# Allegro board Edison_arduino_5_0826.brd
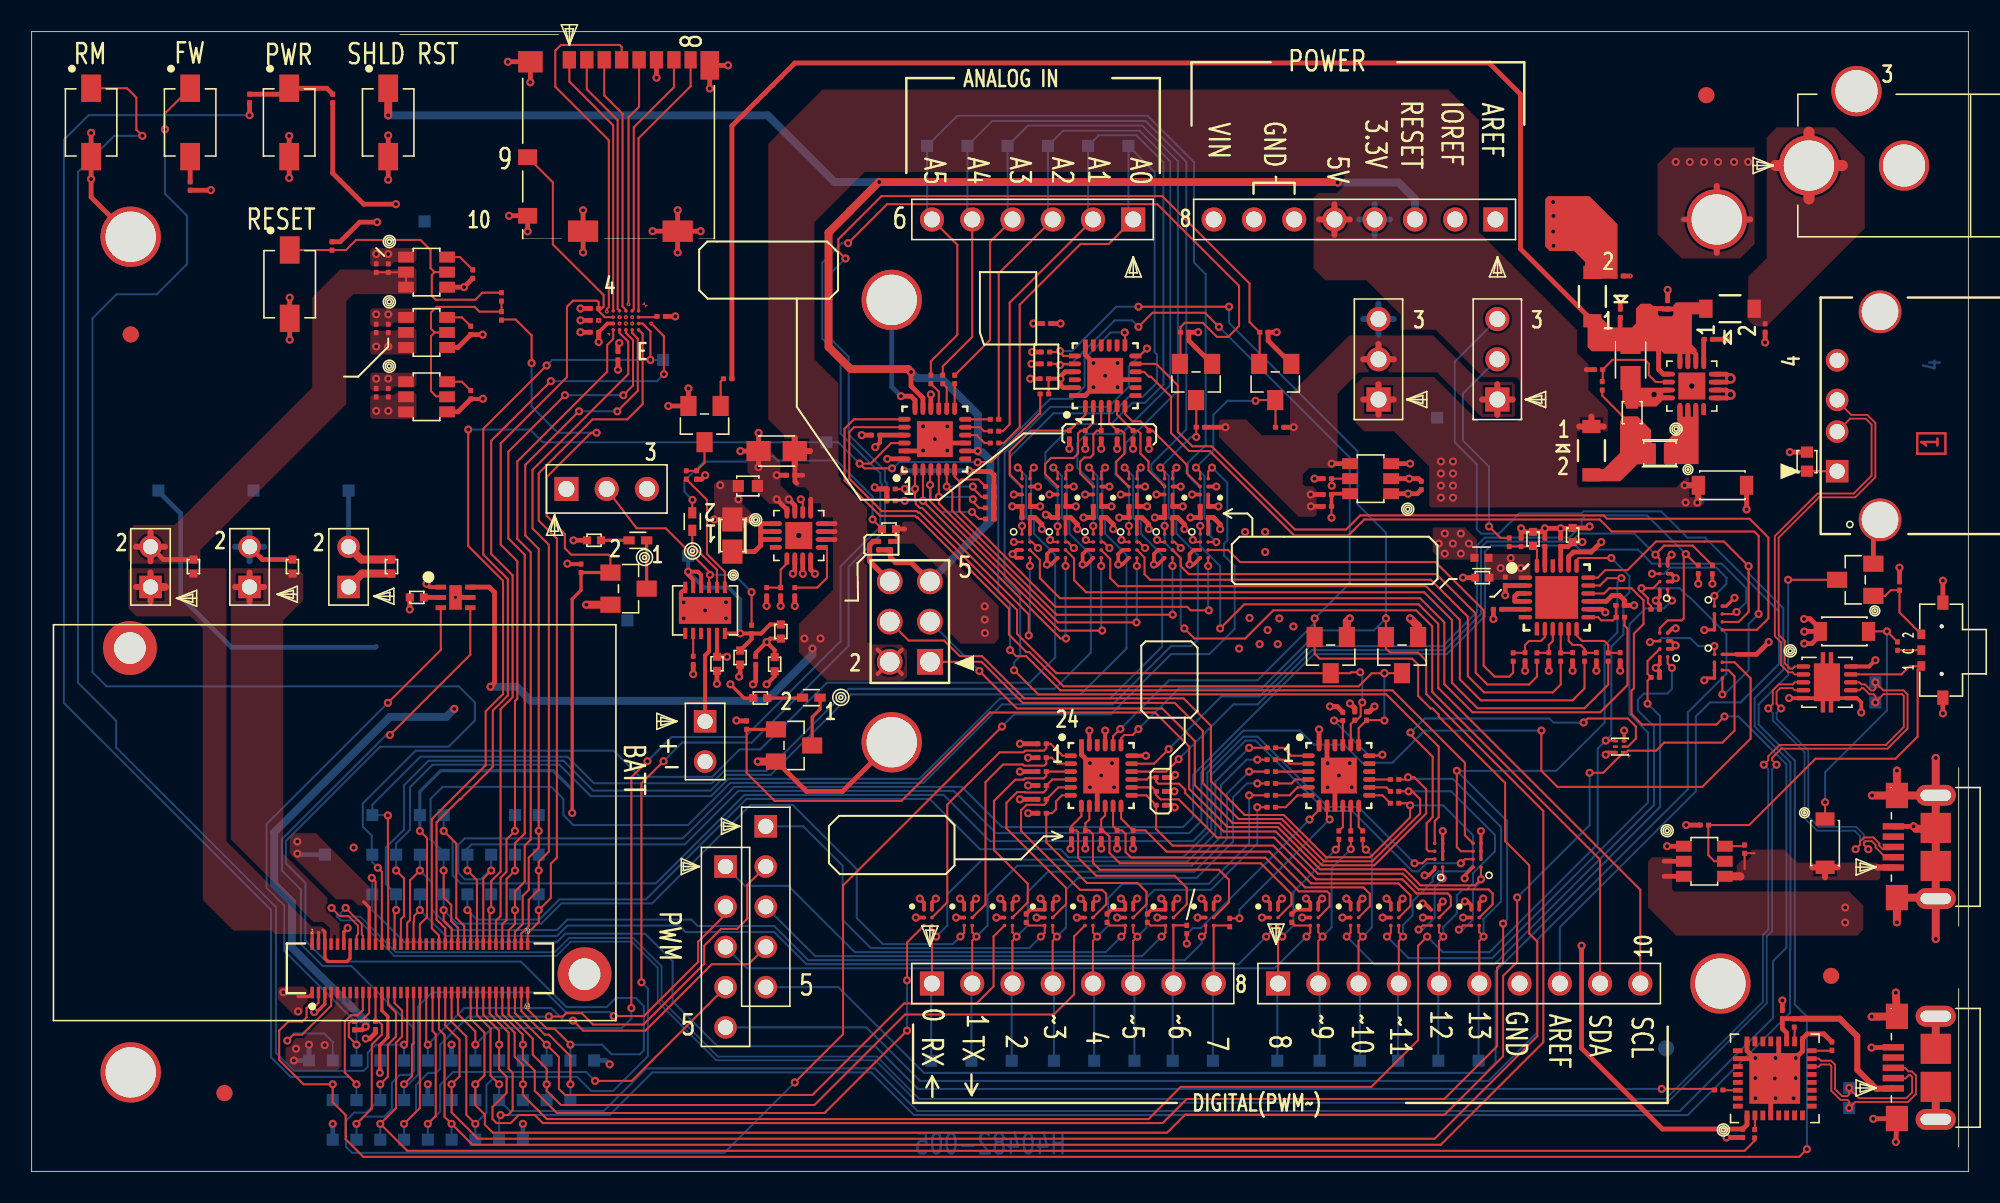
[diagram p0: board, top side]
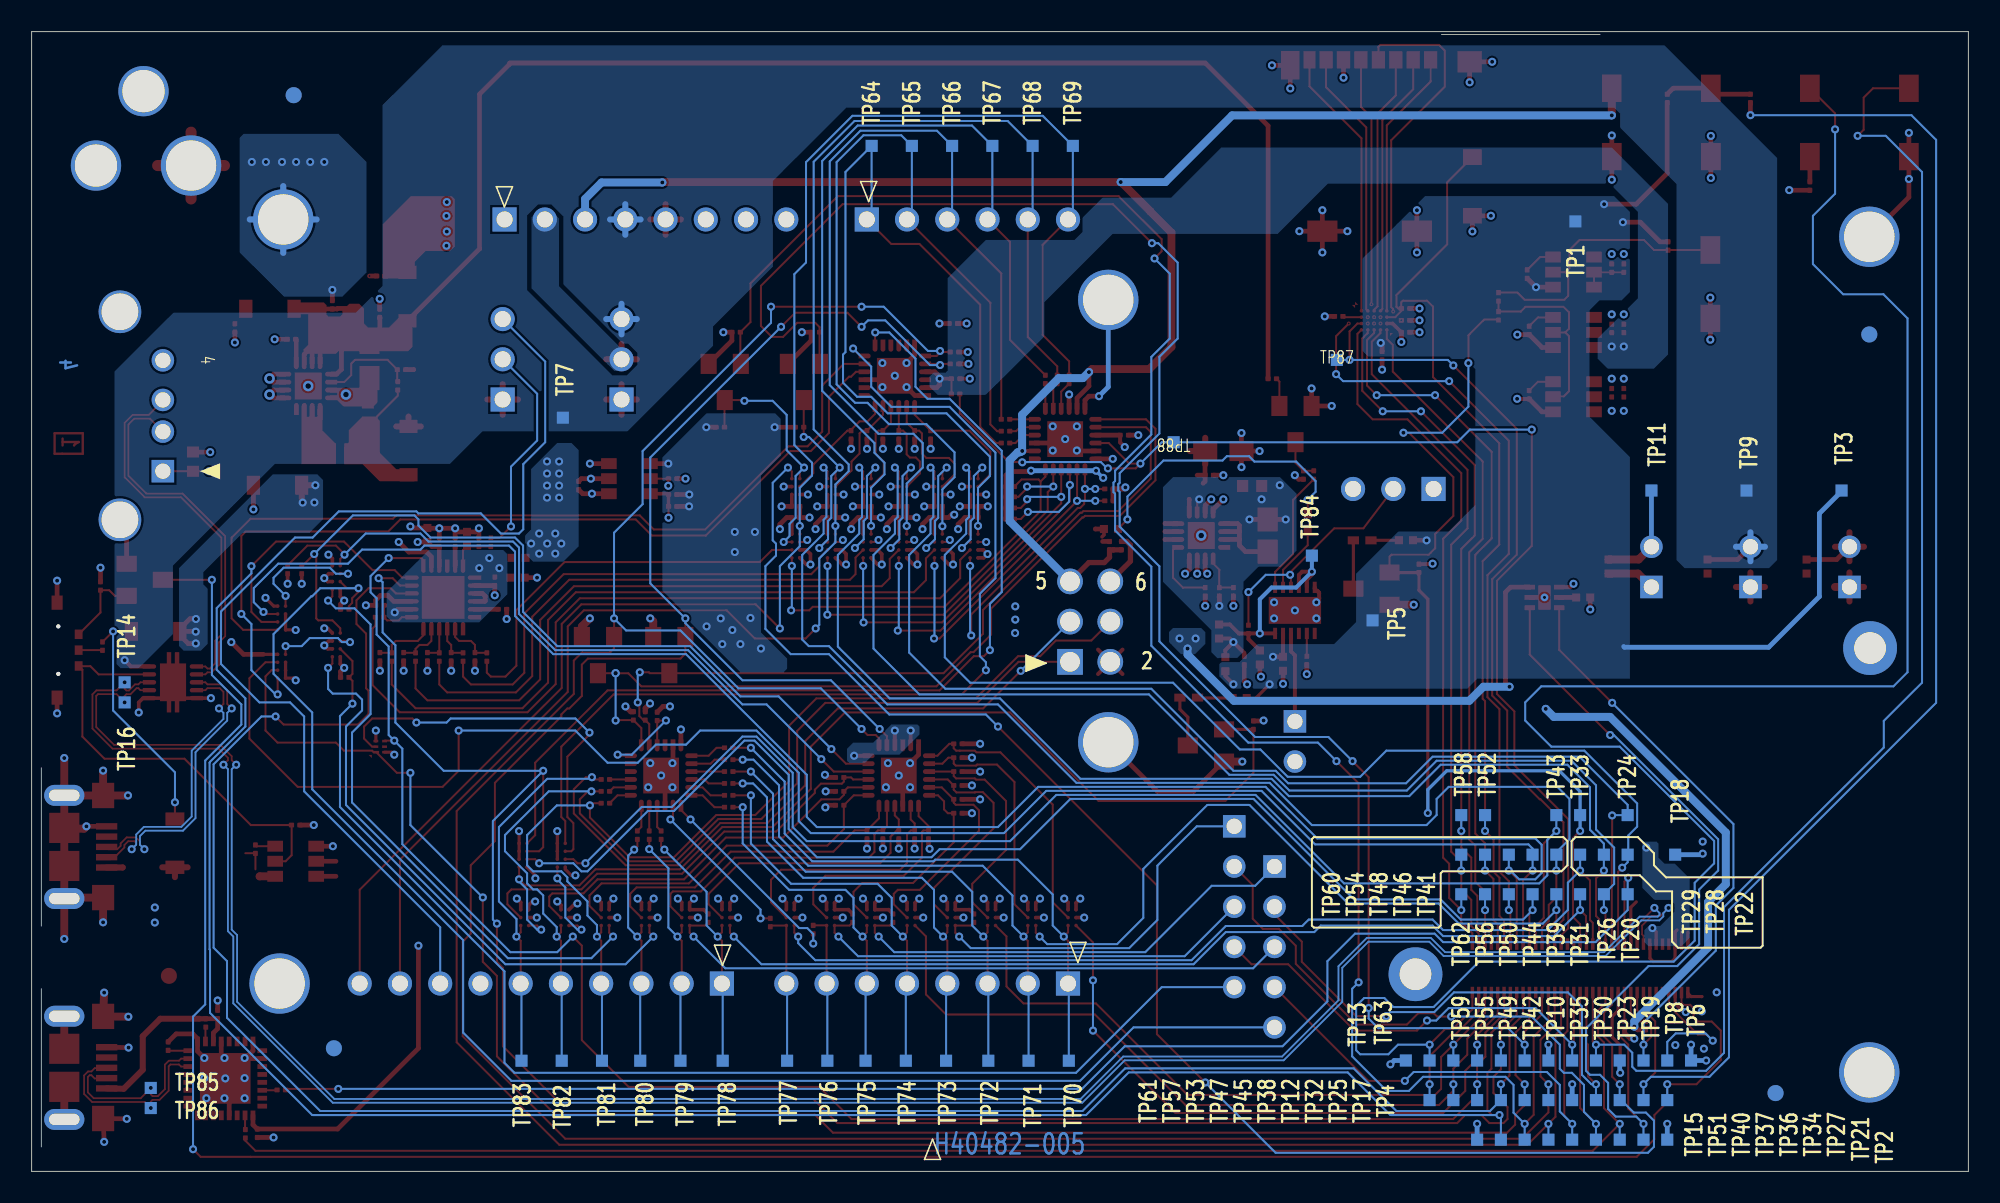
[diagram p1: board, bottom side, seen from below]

Outline 122.22 x 71.98 mm; copper layers: TOP, GND, PWR_GND, BOTTOM. Coordinates in mm from the lower left corner of the outline.
Outline path: 33.25,71.81 23.24,71.81 ; 0,71.98 0,0 122.22,0 122.22,71.98 0,71.98

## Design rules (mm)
constraint set DEFAULT: min track width 0.127
net group DP1: nets N30245034 N30246500
net group PWR_GND: nets V_VBAT_BKUP VBUS_2
net group USB_D: nets USB_DN USB_DP
net group USBA: nets USBA_CONN_DN USBA_CONN_DP
net group USBD: nets N11374 N11378

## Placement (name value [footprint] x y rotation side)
C1  22UF  [SMC0603_HI_VALUE]  101.01 47.32 180 top
C3  0.1uF  [C0201]  103.25 55 0 top
C4  33000pF  [SMC0201]  105.83 52.55 0 top
C5  10uF  [SMC0402]  43.25 32.5 0 top
C6  0.1uF  [C0201]  45.7 32 180 top
C8  10uF  [SMC0402]  44.71 32.9 0 top
C9  0.1uF  [C0201]  110.49 10.17 0 top
C10  0.1uF  [C0201]  107.99 2.14 180 top
C11  10uF  [SMC0402]  92 37.5 270 top
C12  0.1uF  [C0201]  93 37 180 top
C13  10uF  [SMC0402]  97.25 39.75 180 top
C14  0.1uF  [C0201]  96.5 40 0 top
C15  0.1uF  [C0201]  73.75 42 90 top
C16  0.1uF  [C0201]  71.5 42 90 top
C17  0.1uF  [C0201]  69.25 42 90 top
C18  0.1uF  [C0201]  67 42 90 top
C19  0.1uF  [C0201]  64.75 42 90 top
C20  0.1uF  [C0201]  62.5 42 90 top
C21  0.1uF  [C0201]  63.64 50.06 90 top
C22  0.1uF  [C0201]  64.32 53.55 270 top
C23  0.1uF  [C0201]  62.5 41.3 90 top
C24  0.1uF  [C0201]  64.75 41.3 90 top
C25  0.1uF  [C0201]  73.75 41.3 90 top
C26  0.1uF  [C0201]  53 46.5 90 top
C27  0.1uF  [C0201]  82.75 29 0 top
C28  0.1uF  [C0201]  67 41.3 90 top
C29  0.1uF  [C0201]  71.5 41.3 90 top
C30  0.1uF  [C0201]  69.25 41.3 90 top
C31  0.1uF  [C0201]  35.25 53 90 top
C32  0.1uF  [C0201]  37 51.25 180 top
C33  0.1uF  [C0201]  35.25 53.75 90 top
C34  100pF  [SMC0201]  53.45 39.52 90 top
C36  2.2uF  [SMC0603_HI_VALUE]  112.04 44.22 180 top
C40  100pF  [SMC0201]  100.25 35.75 0 top
C41  100pF  [SMC0201]  100.25 32.5 270 top
C42  100pF  [SMC0201]  98.75 32.5 270 top
C43  100pF  [SMC0201]  97.25 32.5 270 top
C44  100pF  [SMC0201]  95.75 32.5 270 top
C45  100pF  [SMC0201]  94.25 32.5 270 top
C46  10uF  [SMC0402]  94.75 39.5 180 top
C47  10uF  [SMC0805]  100.91 52.39 0 top
C48  0.1uF  [C0201]  113.61 8.17 0 top
C49  0.1uF  [C0201]  21.74 57.32 0 top
C50  0.1uF  [C0201]  21.74 53.51 0 top
C51  0.1uF  [C0201]  22.51 49.44 0 top
C52  0.1uF  [C0201]  47.64 43.97 90 top
C53  33000pF  [SMC0201]  48.16 36.6 270 top
C54  22UF  [SMC0603_HI_VALUE]  44.6 43.29 90 top
C55  10uF  [SMC0805]  48.16 45.49 270 top
C56  0.1uF  [C0201]  109.4 53 180 top
C57  0.1uF  [C0201]  100.45 56.55 270 top
CR1  RB160M-40  [SOD123_67X106]  105.18 43.33 90 top
CR2  D2BW319000  [SCR_27X17MA]  98.44 45.52 0 top
CR6  D2BW319000  [SCR_27X17MA]  98.5 55.25 180 top
CR7  D2BW319000  [SCR_27X17MA]  107.19 54.48 90 top
CR8  RB160M-40  [SOD123_67X106]  113.18 22.25 0 top
CR9  RB160M-40  [SOD123_67X106]  115.93 34.1 270 top
DS1  GREEN  [SMLED0402]  38.81 39.85 270 top
DS2  GREEN  [SMLED0402]  49.76 29.92 270 top
DS3  GREEN  [SMLED0402]  41.69 40.49 180 top
EU1  TS3USB221  [LCC10_P5MM_EP65X94]  111.83 31.89 0 top
FB1  120 Ohm@100MHz  [SMF0402]  91.5 38.75 180 top
J1  DC_JACK  [JK_3P_RA]  112.17 63.53 270 top
J1A1  6Pin_HDR  [1X6RCPT_2P54_VT_TH]  63.17 60.12 180 top
J1B1  CON8_HDR  [1X8RCPT_2P54_VT_TH]  65.71 11.86 0 top
J2  CON2_HDR  [102276-001]  42.5 28.42 0 top
J2A1  CON8_HDR  [1X8RCPT_2P54_VT_TH]  83.49 60.12 180 top
J2B1  1x10  [1X10RCPT_2P54_VT_TH]  90.09 11.86 0 top
J3  G58911-001  [RCPT_USB_5P_DIP_SM]  120.17 6.54 90 top
J4  2X3HDR  [CONN6_H18587001]  56.69 32.18 180 top
J5  SD CONN  G46739-001  [CONN_SDCARD_8P_PP]  37.04 64.77 180 top
J6  D23040-001  [CONN4_D23040001]  113.95 44.22 90 top
J7  70Pin BTB  Socket HIROSE DF40  [2X35_P4MM_BTB_AXT_SKT_MB]  17.7 11.29 0 top
J8  CON3_HDR  [102276-003]  92.5 48.75 180 top
J9  CON3_HDR  [102276-003]  85 48.75 180 top
J10  CON2_HDR  [102276-001]  7.5 36.91 180 top
J11  1X5_HDR  [102276-005]  43.79 19.25 0 top
J12  1X5_HDR  [102276-005]  46.33 21.79 0 top
J13  CON3_HDR  [102276-003]  33.75 43.1 90 top
J14  CON2_HDR  [102276-001]  13.75 36.91 180 top
J15  CON2_HDR  [102276-001]  20 36.91 180 top
J16  G58911-001  [RCPT_USB_5P_DIP_SM]  120.17 20.49 90 top
L1  1uH  [SML0805]  103.77 45.35 270 top
L2  1uH  [SML0805]  44.22 39.14 180 top
MGT5  NPTH125  [SYMBOL_NPTH125]  6.25 59.03 0 top
MTG1  -  [NPIN787]  6.2 33.05 0 top
MTG2  -  [NPIN787]  34.89 12.45 0 top
MTG3  NPTH125  [SYMBOL_NPTH125]  106.35 60.12 0 top
MTG4  NPTH125  [SYMBOL_NPTH125]  106.58 11.86 0 top
MTG6  NPTH125  [SYMBOL_NPTH125]  6.25 6.25 0 top
MTG7  NPTH125  [SYMBOL_NPTH125]  54.28 55.04 0 top
MTG8  NPTH125  [SYMBOL_NPTH125]  54.28 27.1 0 top
NOREF  -  []  73.75 38.75 0 top
NOREF#2  -  []  65.25 39.75 90 top
NOREF#3  -  []  66.79 38.54 0 top
NOREF#4  -  []  88.55 19.22 90 top
NOREF#5  -  []  71.5 38.75 0 top
NOREF#6  -  []  62.5 38.75 0 top
NOREF#7  -  []  106.2 31.15 0 top
NOREF#8  -  []  73.54 38.54 0 top
NOREF#9  -  []  0 0 0 top
NOREF#10  -  []  106.7 32.15 90 top
NOREF#11  -  []  102.75 34 0 top
NOREF#12  -  []  102.54 34.21 0 top
NOREF#13  -  []  91.67 19.01 90 top
NOREF#14  -  []  103.46 38.46 270 top
NOREF#15  -  []  105.99 30.95 90 top
NOREF#16  -  []  67 38.75 0 top
NOREF#17  -  []  73.54 38.54 90 top
NOREF#18  -  []  74.25 39.75 90 top
NOREF#19  -  [unnamed#2]  12.17 4.94 0 top
NOREF#20  -  [unnamed#2]  6.25 52.86 0 top
NOREF#21  -  []  103.46 34.21 270 top
NOREF#22  -  []  90.75 20.93 0 top
NOREF#23  -  []  64.54 38.54 0 top
NOREF#24  -  []  71.29 38.54 90 top
NOREF#25  -  []  67.5 39.75 90 top
NOREF#26  -  []  69.25 38.75 0 top
NOREF#27  -  []  69.75 39.75 90 top
NOREF#28  -  []  102.75 33 270 top
NOREF#29  -  []  106.7 35.2 90 top
NOREF#30  -  []  90.96 19.22 90 top
NOREF#31  -  []  89.26 19.01 90 top
NOREF#32  -  []  105.99 33.99 90 top
NOREF#33  -  []  88.55 20.72 0 top
NOREF#34  -  []  105.99 33.99 0 top
NOREF#35  -  []  6.25 6.25 0 top
NOREF#36  -  []  106.35 60.12 0 top
NOREF#37  -  []  63 39.75 90 top
NOREF#38  -  []  71.29 38.54 0 top
NOREF#39  -  []  122.22 71.98 0 top
NOREF#40  -  []  69.04 38.54 0 top
NOREF#41  -  []  105.99 30.95 0 top
NOREF#42  -  []  88.34 20.93 0 top
NOREF#43  -  []  122.22 71.98 0 top
NOREF#44  -  []  90.96 20.72 0 top
NOREF#45  -  []  64.75 38.75 0 top
NOREF#46  -  []  106.35 60.12 0 top
NOREF#47  -  []  0 0 0 top
NOREF#48  -  []  62.29 38.54 90 top
NOREF#49  -  []  64.54 38.54 90 top
NOREF#50  -  []  6.25 6.25 0 top
NOREF#51  -  []  106.2 34.2 0 top
NOREF#52  -  []  72 39.75 90 top
NOREF#53  -  [unnamed#2]  105.69 67.97 0 top
NOREF#54  -  []  102.54 38.46 0 top
NOREF#55  -  []  66.79 38.54 90 top
NOREF#56  -  []  102.75 37.25 270 top
NOREF#57  -  []  102.75 38.25 0 top
NOREF#58  -  [unnamed#2]  113.56 12.35 0 top
NOREF#59  -  []  69.04 38.54 90 top
NOREF#60  -  []  62.29 38.54 0 top
NOREF#61  -  [unnamed#2]  103.15 7.77 180 bottom
NOREF#62  -  [unnamed#2]  105.69 67.97 180 bottom
NOREF#63  -  [unnamed#2]  6.25 52.86 180 bottom
NOREF#64  -  [unnamed#2]  12.17 4.94 180 bottom
Q2  BSS138  [SOT23]  43.48 48.34 270 top
Q3  BSS138  [SOT23]  79.5 51 270 top
Q4  BSS138  [SOT23]  74.5 51 270 top
Q5  BSS138  [SOT23]  83 33.75 270 top
Q6  BSS138  [SOT23]  87.5 33.75 270 top
Q7  FDC6331L  [SOT23_6_SUPER_NOEP_1P22H]  84.5 43.75 180 top
Q8  BSS138  [SOT23]  36.53 37.82 0 top
Q9  BSS138  [SOT23]  46.97 27.91 0 top
Q10  FDC6331L  [SOT23_6_SUPER_NOEP_1P22H]  105.56 19.59 0 top
Q11  BSS138  [SOT23]  116.23 36.35 180 top
Q12  FDC6331L  [SOT23_6_SUPER_NOEP_1P22H]  24.92 48.92 0 top
Q13  FDC6331L  [SOT23_6_SUPER_NOEP_1P22H]  24.92 52.99 0 top
Q14  FDC6331L  [SOT23_6_SUPER_NOEP_1P22H]  24.92 56.8 0 top
R1  0R  [R0201]  99.12 49.88 0 top
R2  0R  [R0201]  99.15 50.64 270 top
R3  10K  [SMR0201]  43.66 50.06 90 top
R4  10K  [SMR0201]  41.75 32 180 top
R5  1K  [R0201]  41.31 44.25 0 top
R6  0R  [R0201]  41.96 44.25 0 top
R7  0R  [R0201]  106.74 5.14 270 top
R8  0R  [R0201]  111.24 9.64 0 top
R9  0R  [R0201]  108.74 2.64 0 top
R10  0R  [R0201]  92.25 35.5 90 top
R11  0R  [R0201]  95.5 40 0 top
R12  10K  [SMR0201]  81.5 42.75 90 top
R13  10K  [SMR0201]  65.49 46.25 180 top
R14  10K  [SMR0201]  66.5 46.25 180 top
R15  10K  [SMR0201]  67.5 46.25 180 top
R16  10K  [SMR0201]  68.5 46.25 180 top
R17  10K  [SMR0201]  69.51 46.25 180 top
R18  10K  [SMR0201]  70.51 46.25 180 top
R19  10K  [SMR0201]  54.2 39.25 180 top
R20  10K  [SMR0201]  63.5 27 90 top
R21  10K  [SMR0201]  63.5 26.13 90 top
R22  10K  [SMR0201]  63.5 25.25 90 top
R23  10K  [SMR0201]  63.5 24.37 90 top
R24  10K  [SMR0201]  63.5 23.5 90 top
R25  10K  [SMR0201]  71.5 24.88 270 top
R26  10K  [SMR0201]  63.5 22.62 90 top
R27  10K  [SMR0201]  71.5 24 270 top
R28  10K  [SMR0201]  65.62 21 180 top
R29  10K  [SMR0201]  71.5 23.12 270 top
R30  10K  [SMR0201]  69.51 21 180 top
R31  10K  [SMR0201]  68.5 21 180 top
R32  10K  [SMR0201]  67.5 21 180 top
R33  10K  [SMR0201]  66.5 21 180 top
R34  10K  [SMR0201]  81.5 42 90 top
R35  10K  [SMR0201]  81.5 43.75 90 top
R36  10K  [SMR0201]  20.37 9.47 0 top
R37  100K  [SMR0201]  21.69 9.48 0 top
R38  576  [SMR0402]  24.75 36.25 270 top
R39  4.7K  [SMR0201]  77.5 53 90 top
R40  4.7K  [SMR0201]  72.5 53 90 top
R41  4.7K  [SMR0201]  78.5 47 90 top
R42  4.7K  [SMR0201]  73.5 47 90 top
R43  4.7K  [SMR0201]  64.25 51 270 top
R44  4.7K  [SMR0201]  64.25 51.75 270 top
R45  10K  [SMR0201]  35.25 54.5 90 top
R46  10K  [SMR0201]  40 54 270 top
R47  220  [SMR0201]  10 62.5 0 top
R48  10K  [SMR0201]  19 67.5 180 top
R49  220  [SMR0201]  13.75 67.5 180 top
R50  4.7K  [SMR0201]  83.5 28.5 180 top
R51  4.7K  [SMR0201]  84.25 28.5 180 top
R52  47K  [SMR0201]  60.5 46 90 top
R53  47K  [SMR0201]  60.5 46.75 90 top
R54  47K  [SMR0201]  60.5 47.5 90 top
R55  47K  [SMR0201]  58.25 49.75 180 top
R56  47K  [SMR0201]  57.5 49.75 180 top
R57  47K  [SMR0201]  56.75 49.75 180 top
R58  47K  [SMR0201]  82.5 21.5 0 top
R59  47K  [SMR0201]  83.25 21.5 0 top
R60  47K  [SMR0201]  84 21.5 0 top
R61  47K  [SMR0201]  85.75 23.25 90 top
R62  47K  [SMR0201]  85.75 24 90 top
R63  47K  [SMR0201]  85.75 24.75 90 top
R64  47K  [SMR0201]  78.5 26.75 270 top
R65  47K  [SMR0201]  78.5 26 270 top
R66  47K  [SMR0201]  78.5 25.25 270 top
R67  47K  [SMR0201]  78.5 24.5 270 top
R68  47K  [SMR0201]  78.5 23.75 270 top
R69  47K  [SMR0201]  78.5 23 270 top
R70  47K  [SMR0201]  72.9 15 180 top
R71  47K  [SMR0201]  75.61 15.98 0 top
R72  2K  [SMR0201]  93.25 40 0 top
R73  2K  [SMR0201]  94 40 0 top
R74  33.2  [SMR0201]  100 35 90 top
R75  33.2  [SMR0201]  99.5 32.75 0 top
R76  33.2  [SMR0201]  98 32.75 0 top
R77  33.2  [SMR0201]  96.5 32.75 0 top
R78  33.2  [SMR0201]  95 32.75 0 top
R79  33.2  [SMR0201]  93.5 32.75 0 top
R80  10K  [SMR0201]  100.26 54.46 0 top
R81  10K  [SMR0201]  45.43 34.5 0 top
R82  100mOhm  [SMR0402]  22.71 38.64 0 top
R83  100mOhm  [SMR0402]  16.46 38.64 0 top
R84  100mOhm  [SMR0402]  10.21 38.64 0 top
R85  10K  [SMR0201]  34.67 37.82 180 top
R86  576  [SMR0402]  35.94 39.86 270 top
R87  10K  [SMR0201]  45.12 27.91 180 top
R88  576  [SMR0402]  46.43 29.9 270 top
R89  47K  [SMR0201]  70.41 15.72 180 top
R90  47K  [SMR0201]  67.87 15.72 180 top
R91  47K  [SMR0201]  62.76 15.72 180 top
R92  47K  [SMR0201]  79.53 15.72 180 top
R93  47K  [SMR0201]  102.2 35.5 90 top
R94  47K  [SMR0201]  102.2 31.2 90 top
R95  10K  [SMR0201]  105.3 21.87 90 top
R96  10K  [SMR0201]  108.1 20.08 180 top
R97  10K  [SMR0201]  117.76 32.91 180 top
R98  10K  [SMR0201]  117.88 37.24 0 top
R100  10K  [SMR0201]  27.71 48.78 180 top
R102  10K  [SMR0201]  27.71 52.85 180 top
R104  10K  [SMR0201]  27.84 56.4 180 top
R105  10K  [SMR0201]  18.95 58.71 0 top
R106  10K  [SMR0201]  22.51 56.78 180 top
R107  10K  [SMR0201]  22.51 52.97 180 top
R108  4.7K  [SMR0201]  21.74 48.91 180 top
R109  10K  [SMR0201]  106.07 37.75 180 top
R110  10K  [SMR0201]  105.18 37.75 180 top
R111  47K  [SMR0201]  47.27 36.87 0 top
R112  10.5K  [SMR0201]  46.38 36.34 180 top
R113  100mOhm  [SMR0402]  46.89 32.48 0 top
R114  576  [SMR0402]  53.66 40.57 90 top
R115  100mOhm  [SMR0402]  47.28 33.65 180 top
R116  47K  [SMR0201]  54.5 43.1 270 top
R117  47K  [SMR0201]  54.5 42.35 270 top
R118  47K  [SMR0201]  60.2 41.2 90 top
R119  47K  [SMR0201]  60.2 41.9 90 top
R120  47K  [SMR0201]  60.2 42.6 90 top
R121  47K  [SMR0201]  60.2 43.25 90 top
R122  4.7K  [SMR0201]  63.65 49.1 90 top
R123  0R  [R0201]  29.65 54.3 0 top
R124  0R  [R0201]  29.65 55.5 0 top
R125  4.7K  [SMR0201]  87.7 43.05 180 top
SW1  Slide switch,SSAJ110100  [SW_SSAJ110100_3P]  119.26 32.92 90 top
SW1UI1  LIGHT TOUCH SWITCH EVQP7J01P  [SSW2RPB]  22.5 66.25 0 top
SW1UI2  LIGHT TOUCH SWITCH EVQP7J01P  [SSW2RPB]  16.25 66.25 0 top
SW1UI3  LIGHT TOUCH SWITCH EVQP7J01P  [SSW2RPB]  10 66.25 0 top
SW1UI4  LIGHT TOUCH SWITCH EVQP7J01P  [SSW2RPB]  3.75 66.25 0 top
SW1UI5  LIGHT TOUCH SWITCH EVQP7J01P  [SSW2RPB]  16.28 56.03 0 top
TP1  30 MIL TESTPAD  [TP30S]  24.8 60 180 bottom
TP2  30 MIL TESTPAD  [TP30S]  19 2 180 bottom
TP3  30 MIL TESTPAD  [TP30S]  8 43 180 bottom
TP4  30 MIL TESTPAD  [TP30S]  19 4.5 180 bottom
TP5  30 MIL TESTPAD  [TP30S]  37.6 34.8 180 bottom
TP6  30 MIL TESTPAD  [TP30S]  17.5 7 180 bottom
TP7  30 MIL TESTPAD  [TP30S]  88.7 47.6 180 bottom
TP8  30 MIL TESTPAD  [TP30S]  19 7 180 bottom
TP9  30 MIL TESTPAD  [TP30S]  14 43 180 bottom
TP10  30 MIL TESTPAD  [TP30S]  26.5 7 180 bottom
TP11  30 MIL TESTPAD  [TP30S]  20 43 180 bottom
TP12  30 MIL TESTPAD  [TP30S]  25 4.5 180 bottom
TP13  30 MIL TESTPAD  [TP30S]  35.5 7 180 bottom
TP14  30 MIL TESTPAD  [TP30S]  116.36 30.89 180 bottom
TP15  30 MIL TESTPAD  [TP30S]  31 2 180 bottom
TP16  30 MIL TESTPAD  [TP30S]  116.36 29.62 180 bottom
TP17  30 MIL TESTPAD  [TP30S]  20.5 4.5 180 bottom
TP18  30 MIL TESTPAD  [TP30S]  18.5 20 180 bottom
TP19  30 MIL TESTPAD  [TP30S]  20.5 7 180 bottom
TP20  30 MIL TESTPAD  [TP30S]  21.5 17.5 180 bottom
TP21  30 MIL TESTPAD  [TP30S]  20.5 2 180 bottom
TP22  30 MIL TESTPAD  [TP30S]  21.5 20 180 bottom
TP23  30 MIL TESTPAD  [TP30S]  22 7 180 bottom
TP24  30 MIL TESTPAD  [TP30S]  21.5 22.5 180 bottom
TP25  30 MIL TESTPAD  [TP30S]  22 4.5 180 bottom
TP26  30 MIL TESTPAD  [TP30S]  23 17.5 180 bottom
TP27  30 MIL TESTPAD  [TP30S]  22 2 180 bottom
TP28  30 MIL TESTPAD  [TP30S]  23 20 180 bottom
TP29  30 MIL TESTPAD  [TP30S]  24.5 20 180 bottom
TP30  30 MIL TESTPAD  [TP30S]  23.5 7 180 bottom
TP31  30 MIL TESTPAD  [TP30S]  24.5 17.5 180 bottom
TP32  30 MIL TESTPAD  [TP30S]  23.5 4.5 180 bottom
TP33  30 MIL TESTPAD  [TP30S]  24.5 22.5 180 bottom
TP34  30 MIL TESTPAD  [TP30S]  23.5 2 180 bottom
TP35  30 MIL TESTPAD  [TP30S]  25 7 180 bottom
TP36  30 MIL TESTPAD  [TP30S]  25 2 180 bottom
TP37  30 MIL TESTPAD  [TP30S]  26.5 2 180 bottom
TP38  30 MIL TESTPAD  [TP30S]  26.5 4.5 180 bottom
TP39  30 MIL TESTPAD  [TP30S]  26 17.5 180 bottom
TP40  30 MIL TESTPAD  [TP30S]  28 2 180 bottom
TP41  30 MIL TESTPAD  [TP30S]  26 20 180 bottom
TP42  30 MIL TESTPAD  [TP30S]  28 7 180 bottom
TP43  30 MIL TESTPAD  [TP30S]  26 22.5 180 bottom
TP44  30 MIL TESTPAD  [TP30S]  27.5 17.5 180 bottom
TP45  30 MIL TESTPAD  [TP30S]  28 4.5 180 bottom
TP46  30 MIL TESTPAD  [TP30S]  27.5 20 180 bottom
TP47  30 MIL TESTPAD  [TP30S]  29.5 4.5 180 bottom
TP48  30 MIL TESTPAD  [TP30S]  29 20 180 bottom
TP49  30 MIL TESTPAD  [TP30S]  29.5 7 180 bottom
TP50  30 MIL TESTPAD  [TP30S]  29 17.5 180 bottom
TP51  30 MIL TESTPAD  [TP30S]  29.5 2 180 bottom
TP52  30 MIL TESTPAD  [TP30S]  30.5 22.5 180 bottom
TP53  30 MIL TESTPAD  [TP30S]  31 4.5 180 bottom
TP54  30 MIL TESTPAD  [TP30S]  30.5 20 180 bottom
TP55  30 MIL TESTPAD  [TP30S]  31 7 180 bottom
TP56  30 MIL TESTPAD  [TP30S]  30.5 17.5 180 bottom
TP57  30 MIL TESTPAD  [TP30S]  32.5 4.5 180 bottom
TP58  30 MIL TESTPAD  [TP30S]  32 22.5 180 bottom
TP59  30 MIL TESTPAD  [TP30S]  32.5 7 180 bottom
TP60  30 MIL TESTPAD  [TP30S]  32 20 180 bottom
TP61  30 MIL TESTPAD  [TP30S]  34 4.5 180 bottom
TP62  30 MIL TESTPAD  [TP30S]  32 17.5 180 bottom
TP63  30 MIL TESTPAD  [TP30S]  34 7 180 bottom
TP64  30 MIL TESTPAD  [TP30S]  69.22 64.77 180 bottom
TP65  30 MIL TESTPAD  [TP30S]  66.67 64.77 180 bottom
TP66  30 MIL TESTPAD  [TP30S]  64.13 64.77 180 bottom
TP67  30 MIL TESTPAD  [TP30S]  61.59 64.77 180 bottom
TP68  30 MIL TESTPAD  [TP30S]  59.05 64.77 180 bottom
TP69  30 MIL TESTPAD  [TP30S]  56.52 64.77 180 bottom
TP70  30 MIL TESTPAD  [TP30S]  56.77 6.99 180 bottom
TP71  30 MIL TESTPAD  [TP30S]  59.31 6.99 180 bottom
TP72  30 MIL TESTPAD  [TP30S]  61.85 6.99 180 bottom
TP73  30 MIL TESTPAD  [TP30S]  64.52 6.99 180 bottom
TP74  30 MIL TESTPAD  [TP30S]  67.06 6.99 180 bottom
TP75  30 MIL TESTPAD  [TP30S]  69.6 6.99 180 bottom
TP76  30 MIL TESTPAD  [TP30S]  72.01 6.99 180 bottom
TP77  30 MIL TESTPAD  [TP30S]  74.55 6.99 180 bottom
TP78  30 MIL TESTPAD  [TP30S]  78.61 6.99 180 bottom
TP79  30 MIL TESTPAD  [TP30S]  81.28 6.99 180 bottom
TP80  30 MIL TESTPAD  [TP30S]  83.82 6.99 180 bottom
TP81  30 MIL TESTPAD  [TP30S]  86.23 6.99 180 bottom
TP82  30 MIL TESTPAD  [TP30S]  88.77 6.99 180 bottom
TP83  30 MIL TESTPAD  [TP30S]  91.31 6.99 180 bottom
TP84  30 MIL TESTPAD  [TP30S]  41.43 38.89 180 bottom
TP85  30 MIL TESTPAD  [TP30S]  114.71 5.27 180 bottom
TP86  30 MIL TESTPAD  [TP30S]  114.71 4 180 bottom
TP87  30 MIL TESTPAD  [TP30S]  39.85 51.25 180 bottom
TP88  30 MIL TESTPAD  [TP30S]  50.15 46.05 0 bottom
U1  TPS62133  [LCC16_3X3MM_67DIE_39H]  104.77 49.6 90 top
U2  FT232R  [LCC32_P5MM_3P2SQ_NONC]  110.01 5.87 90 top
U3  ADS7951  [QFN24P_5M_4X4M]  96.25 36.25 0 top
U4  74LVC1T45 CSP  [BGA6_5MM_37X57]  74 43.25 180 top
U5  74LVC2G53 CSP  [BGA8P_5MG2X4]  74 39.5 0 top
U6  74LVC1T45 CSP  [BGA6_5MM_37X57]  71.75 43.25 180 top
U7  74LVC2G53 CSP  [BGA8P_5MG2X4]  71.75 39.5 0 top
U8  74LVC1T45 CSP  [BGA6_5MM_37X57]  69.5 43.25 180 top
U9  74LVC2G53 CSP  [BGA8P_5MG2X4]  69.5 39.5 0 top
U10  74LVC1T45 CSP  [BGA6_5MM_37X57]  67.25 43.25 180 top
U11  74LVC2G53 CSP  [BGA8P_5MG2X4]  67.25 39.5 0 top
U12  74LVC1T45 CSP  [BGA6_5MM_37X57]  65 43.25 180 top
U13  74LVC2G53 CSP  [BGA8P_5MG2X4]  65 39.5 0 top
U14  74LVC1T45 CSP  [BGA6_5MM_37X57]  62.75 43.25 180 top
U15  74LVC2G53 CSP  [BGA8P_5MG2X4]  62.75 39.5 0 top
U16  PCAL9555  [LCC25_S41_5DF89X89MA]  67.75 50.25 90 top
U17  PCAL9535A  [LCC25_S41_5DF89X89MA]  57 46.25 90 top
U18  74LVC1T45 CSP  [BGA6_5MM_37X57]  91.11 16.03 0 top
U19  74LVC1T45 CSP  [BGA6_5MM_37X57]  71.81 16.03 0 top
U20  74LVC1T45 CSP  [BGA6_5MM_37X57]  88.57 16.03 0 top
U21  74LVC1T45 CSP  [BGA6_5MM_37X57]  69.27 16.03 0 top
U22  74LVC2G53 CSP  [BGA8P_5MG2X4]  103 37.5 180 top
U23  74LVC1T45 CSP  [BGA6_5MM_37X57]  86.03 16.03 0 top
U24  74LVC1T45 CSP  [BGA6_5MM_37X57]  66.73 16.03 0 top
U25  74LVC2G53 CSP  [BGA8P_5MG2X4]  103 33.25 180 top
U26  74LVC1T45 CSP  [BGA6_5MM_37X57]  83.49 16.03 0 top
U27  74LVC1T45 CSP  [BGA6_5MM_37X57]  64.19 16.03 0 top
U28  74LVC1T45 CSP  [BGA6_5MM_37X57]  80.95 16.03 0 top
U29  74LVC1T45 CSP  [BGA6_5MM_37X57]  61.65 16.03 0 top
U30  74LVC1T45 CSP  [BGA6_5MM_37X57]  78.41 16.03 0 top
U31  74LVC1T45 CSP  [BGA6_5MM_37X57]  59.11 16.03 0 top
U32  74LVC1T45 CSP  [BGA6_5MM_37X57]  74.35 16.03 0 top
U33  74LVC1T45 CSP  [BGA6_5MM_37X57]  56.57 16.03 0 top
U34  PCAL9555  [LCC25_S41_5DF89X89MA]  67.5 25 0 top
U35  TXS206-29  [BGA20_P4MM_1P96X1P56]  37.5 53.75 90 top
U36  MIC2039  [DFN6P_65M_2X2M]  26.75 36.25 0 top
U38  LTC4067  [LCC12_P5MM_3X4MM]  43.75 36.89 180 top
U39  PCAL9535A  [LCC25_S41_5DF89X89MA]  82.5 25 0 top
U40  74LVC2G53 CSP  [BGA8P_5MG2X4]  106.45 31.9 0 top
U41  74LVC2G53 CSP  [BGA8P_5MG2X4]  106.45 34.95 0 top
U42  74LVC2G53 CSP  [BGA8P_5MG2X4]  88.8 19.97 180 top
U43  74LVC2G53 CSP  [BGA8P_5MG2X4]  91.21 19.97 180 top
U44  74AUP1G125  [LCC6_P35MM_SQ1P0_NONC_P5H]  100.23 26.82 90 top
U45  TPS62130  [LCC16_3X3MM_67DIE_39H]  48.41 40.16 0 top

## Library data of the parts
C1 C54 = CAPC,X5R,0603,6.3V,20%,22UF
C3 C6 C9 C10 C12 C14-C33 C48-C52 C56 C57 = CAP
C4 C53 = CAPC,X5R,0201,6.3V,10%,33000pF
C5 C8 C11 C13 C46 = CAPC,X5R,0402,6.3V,20%,10uF: tolerance: 20%
C34 C40-C45 = CAPC,COG,0201,25V,5%,100pF: room: BATTERY
C36 = CAPC,X5R,0603,25V,10%,2.2uF: tolerance: 10%; room: USB
C47 C55 = CAPC,X7R,0805,50V,10%,1.0uF: tolerance: 10%
CR1 CR8 CR9 = DIO,SHTKY,SOD123,RB160M-40
CR2 CR6 CR7 = DIO,SHTKY,DB2W319000L
DS1-DS3 = LED,SMT,GREEN,V,0402
EU1 = IC,TS3USB221,SON10,MPlex_0: room: NO_ROOM
FB1 = FERBD,0402,120Ohm_100MHz,1.3A: room: AUDIO_SPKR
J1 = TMP_091753
J1A1 = CON6,HDR,TH,0.1in,C77962-001: room: NO_ROOM
J1B1 J2A1 = CON8,HDR,TH,0.1in,E70026-001
J2 J10 J14 J15 = CON2,HDR,TH,0.1in,A91829-020
J2B1 = CON10,1X10,0.1,0.093,E74918-001: room: NO_ROOM
J3 J16 = CON4,USB,RA,_1
J4 = CON6,HDR,TH,0_0.1,C77978-007
J5 = CON8,MICROSD,NOACO_4
J6 = CON4,USB,RA,_4
J7 = CON70,SKT,SM,4mm,AXT570124_0: room: NO_ROOM
J8 J9 J13 = CON3,HDR,TH,0.1in,A91829-009
J11 J12 = CON5,HDR,TH,100mil,A91829-006
L1 L2 = INDCT,1uH,1.1A,30%,0805: tolerance: 30%; room: NO_ROOM
MGT5 MTG3 MTG4 MTG6-MTG8 = symbol_npth125_0
MTG1 MTG2 = MOUNTING HOLE 787
Q2-Q6 Q8 Q9 Q11 = XSTR,BSS138,FET,NCH,SOT23
Q7 Q10 Q12-Q14 = IC,FDC6331,LOADSWI
R1 R2 R6-R11 R123 R124 = R_0
R3 R4 R12-R36 R80 R81 R85 R87 R95-R98 R100 R102 R104-R107 R109 R110 = RESD,0201,5%,1/20W,10K: tolerance: 5%; room: AUDIO_CODEC
R5 = R0603
R37 = RESD,0201,5%,1/20W,100K: tolerance: 5%; room: APE_PMIC_MISC
R38 R86 R88 R114 = RESD,0201,1%,1/20W,562: tolerance: 1%
R39-R44 R50 R51 R108 R122 R125 = RESD,0201,5%,1/20W,4.7K: tolerance: 5%; room: APE_PMIC_MISC
R45 R46 R48 = RESD,0201,5%,1/20W,10K: tolerance: 5%; room: USB
R47 R49 = RESD,0201,5%,1/20W,220: tolerance: 5%; room: UI_BUTTONS
R52-R71 R89-R94 R111 R112 R116-R121 = RESD,0201,1%,1/20W,47K: tolerance: 1%
R72 R73 = RESD,0201,1%,1/20W,2K: tolerance: 1%; room: APE_PMIC_MISC
R74-R79 = RESD,0201,1%,1/20W,33.2: tolerance: 1%
R82-R84 R113 R115 = RESD,0402,1%,1/16W,100mOhm: tolerance: 1%
SW1 = SWCH,Slide,SPST,SMT,SSAJ110100: room: NO_ROOM
SW1UI1-SW1UI5 = SWITCH,EVQP7J01P,4P,PWR_0: room: UI_BUTTONS
TP1-TP88 = TestPad,C80,SMT: room: TEST_APE
U1 U45 = TPS62133_0
U2 = FT232R_0
U3 = ads7959_0: User Part Number: H40908-001; Tolerance: XXX
U4 U6 U8 U10 U12 U14 U18-U21 U23 U24 U26-U33 = IC,74LVC1T45,LOG,BGA6,TRNSSVR
U5 U7 U9 U11 U13 U15 U22 U25 U40-U43 = IC,74LVC2G53: Tolerance: XXX; User Part Number: H40914-001
U16 U34 = IC,PCAL9555,16bit_GPIO
U17 U39 = IC,PCAL9535a,16bit_GPIO
U35 = TXS0206-29
U36 = IC,MIC2039,UsbPwrSwtch_0: User Part Number: H40907-001; Tolerance: XXX; room: NO_ROOM
U38 = IC,LTC4067,QFN12,USB_PWR_MNGR_1
U44 = IC,74AUP1G125,LOG,LCC6,BUFFER: room: NO_ROOM

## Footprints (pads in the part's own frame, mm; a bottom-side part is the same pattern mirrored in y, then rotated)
1X6RCPT_2P54_VT_TH
  rect 1.524x1.524 hole 1.016: 1(-6.35,0)
  round 1.524 hole 1.016: 2(-3.81,0) 3(-1.27,0) 4(1.27,0) 5(3.81,0) 6(6.35,0)
1X8RCPT_2P54_VT_TH
  rect 1.524x1.524 hole 1.016: 1(-8.89,0)
  round 1.524 hole 1.016: 2(-6.35,0) 3(-3.81,0) 4(-1.27,0) 5(1.27,0) 6(3.81,0) 7(6.35,0) 8(8.89,0)
1X10RCPT_2P54_VT_TH
  rect 1.524x1.524 hole 1.016: 1(-11.43,0)
  round 1.524 hole 1.016: 2(-8.89,0) 3(-6.35,0) 4(-3.81,0) 5(-1.27,0) 6(1.27,0) 7(3.81,0) 8(6.35,0) 9(8.89,0) 10(11.43,0)
2X35_P4MM_BTB_AXT_SKT_MB
  rect 0.22x0.728 smd: 1(0,0) 2(0,3.058) 3(0.4,0) 4(0.4,3.058) 5(0.8,0) 6(0.8,3.058) 7(1.2,0) 8(1.2,3.058) 9(1.6,0) 10(1.6,3.058) 11(2,0) 12(2,3.058) 13(2.4,0) 14(2.4,3.058) 15(2.8,0) 16(2.8,3.058) 17(3.2,0) 18(3.2,3.058) 19(3.6,0) 20(3.6,3.058) 21(4,0) 22(4,3.058) 23(4.4,0) 24(4.4,3.058) 25(4.8,0) 26(4.8,3.058) 27(5.2,0) 28(5.2,3.058) 29(5.6,0) 30(5.6,3.058) 31(6,0) 32(6,3.058) 33(6.4,0) 34(6.4,3.058) 35(6.8,0) 36(6.8,3.058) 37(7.2,0) 38(7.2,3.058) 39(7.6,0) 40(7.6,3.058) 41(8,0) 42(8,3.058) 43(8.4,0) 44(8.4,3.058) 45(8.8,0) 46(8.8,3.058) 47(9.2,0) 48(9.2,3.058) 49(9.6,0) 50(9.6,3.058) 51(10,0) 52(10,3.058) 53(10.4,0) 54(10.4,3.058) 55(10.8,0) 56(10.8,3.058) 57(11.2,0) 58(11.2,3.058) 59(11.6,0) 60(11.6,3.058) 61(12,0) 62(12,3.058) 63(12.4,0) 64(12.4,3.058) 65(12.8,0) 66(12.8,3.058) 67(13.2,0) 68(13.2,3.058) 69(13.6,0) 70(13.6,3.058)
102276-001
  rect 1.422x1.422 hole 0.965: 1(0,0)
  round 1.422 hole 0.965: 2(0,-2.54)
102276-003
  rect 1.524x1.524 hole 1.016: 1(0,0)
  round 1.524 hole 1.016: 2(0,-2.54) 3(0,-5.08)
102276-005
  rect 1.422x1.422 hole 0.965: 1(0,0)
  round 1.422 hole 0.965: 2(0,-2.54) 3(0,-5.08) 4(0,-7.62) 5(0,-10.16)
BGA6_5MM_37X57
  round 0.229 smd: A1(-0.252,0.5) A2(0.252,0.5) B1(-0.252,0) B2(0.252,0) C1(-0.252,-0.5) C2(0.252,-0.5)
BGA8P_5MG2X4
  round 0.229 smd: A1(-0.25,0.75) A2(0.25,0.75) B1(-0.25,0.25) B2(0.25,0.25) C1(-0.25,-0.25) C2(0.25,-0.25) D1(-0.25,-0.75) D2(0.25,-0.75)
BGA20_P4MM_1P96X1P56
  round 0.229 smd: A1(-0.6,0.8) A2(-0.2,0.8) A3(0.2,0.8) A4(0.6,0.8) B1(-0.6,0.4) B2(-0.2,0.4) B3(0.2,0.4) B4(0.6,0.4) C1(-0.6,0) C2(-0.2,0) C3(0.2,0) C4(0.6,0) D1(-0.6,-0.4) D2(-0.2,-0.4) D3(0.2,-0.4) D4(0.6,-0.4) E1(-0.6,-0.8) E2(-0.2,-0.8) E3(0.2,-0.8) E4(0.6,-0.8)
C0201
  custom 0.076x0.076 smd: 1(0,0) 2(0,-0.533)
CONN4_D23040001
  rect 1.422x1.422 hole 0.965: 1(0,0)
  round 1.422 hole 0.965: 2(2.5,0) 3(4.5,0) 4(7,0)
  round 2.692 hole 2.311: MH1(-3.071,-2.71) MH2(10.069,-2.71)
CONN6_H18587001
  rect 1.626x1.626 hole 1.245: 1(0,0)
  round 1.626 hole 1.245: 2(2.54,0) 3(0,-2.54) 4(2.54,-2.54) 5(0,-5.08) 6(2.54,-5.08)
CONN_SDCARD_8P_PP
  rect 0.838x1.092 smd: 1(3.105,-5.434) 2(2.005,-5.434) 3(0.905,-5.434) 4(-0.195,-5.434) 5(-1.295,-5.434) 6(-2.395,-5.434) 7(-3.495,-5.434)
  rect 0.762x1.092 smd: 8(-4.545,-5.434)
  rect 1.194x0.991 smd: 9(5.74,0.716) 10(5.74,4.416)
  rect 1.549x1.346 smd: G1(5.565,-5.309)
  rect 1.168x1.803 smd: G2(-5.755,-5.084)
  rect 1.905x1.346 smd: G3(-3.73,5.391) G4(2.24,5.391)
DFN6P_65M_2X2M
  rect 0.66x0.305 smd: 1(-0.93,0.65) 2(-0.93,0) 3(-0.93,-0.65) 4(0.93,-0.65) 5(0.93,0) 6(0.93,0.65)
  rect 0.787x1.549 smd: 7(0,0)
JK_3P_RA
  round 3.81 hole 3.175: 1(0,0)
  round 3.175 hole 2.667: 2(0,6) 3(-4.7,3)
LCC6_P35MM_SQ1P0_NONC_P5H
  rect 0.16x0.36 smd: 1(-0.35,-0.25)
  rect 0.16x0.31 smd: 2(0,-0.275) 3(0.35,-0.275) 4(0.35,0.275) 5(0,0.275) 6(-0.35,0.275)
LCC10_P5MM_EP65X94
  custom 0.07x0.07 smd: 1(0,0) 2(0,-0.5) 3(0,-1) 4(0,-1.5) 5(0,-2) 6(2.959,-2) 7(2.959,-1.5) 8(2.959,-1) 9(2.959,-0.5) 10(2.959,0)
  custom 0.413x0.413 smd: 11(1.473,-1)
LCC12_P5MM_3X4MM
  rect 0.254x0.711 smd: 1(0,0) 2(0.5,0) 3(1.001,0) 4(1.501,0) 5(2.002,0) 6(2.499,0) 7(2.499,2.911) 8(2.002,2.911) 9(1.501,2.911) 10(1.001,2.911) 11(0.5,2.911) 12(0,2.911)
  rect 3.302x1.702 smd: 13(1.25,1.455)
LCC16_3X3MM_67DIE_39H
  custom 0.076x0.076 smd: 1(-1.448,0.752) 2(-1.448,0.252) 3(-1.448,-0.249) 4(-1.448,-0.749) 5(-0.752,-1.448) 6(-0.252,-1.448) 7(0.249,-1.448) 8(0.749,-1.448) 9(1.448,-0.752) 10(1.448,-0.252) 11(1.448,0.249) 12(1.448,0.749) 13(0.752,1.448) 14(0.252,1.448) 15(-0.249,1.448) 16(-0.749,1.448)
  rect 1.702x1.702 smd: 17(0,0)
LCC25_S41_5DF89X89MA
  custom 0.076x0.076 smd: 1(-1.905,1.25) 2(-1.905,0.75) 3(-1.905,0.25) 4(-1.905,-0.25) 5(-1.905,-0.75) 6(-1.905,-1.25) 7(-1.25,-1.905) 8(-0.75,-1.905) 9(-0.25,-1.905) 10(0.25,-1.905) 11(0.75,-1.905) 12(1.25,-1.905) 13(1.905,-1.25) 14(1.905,-0.75) 15(1.905,-0.25) 16(1.905,0.25) 17(1.905,0.75) 18(1.905,1.25) 19(1.25,1.905) 20(0.75,1.905) 21(0.25,1.905) 22(-0.25,1.905) 23(-0.75,1.905) 24(-1.25,1.905)
  rect 2.261x2.261 smd: 25(0,0)
LCC32_P5MM_3P2SQ_NONC
  rect 0.61x0.305 smd: 1(-2.334,1.75) 2(-2.334,1.25) 3(-2.334,0.749) 4(-2.334,0.252) 5(-2.334,-0.249) 6(-2.334,-0.749) 7(-2.334,-1.25) 8(-2.334,-1.75) 17(2.334,-1.75) 18(2.334,-1.25) 19(2.334,-0.749) 20(2.334,-0.252) 21(2.334,0.249) 22(2.334,0.749) 23(2.334,1.25) 24(2.334,1.75)
  rect 0.305x0.61 smd: 9(-1.75,-2.334) 10(-1.25,-2.334) 11(-0.749,-2.334) 12(-0.252,-2.334) 13(0.249,-2.334) 14(0.749,-2.334) 15(1.25,-2.334) 16(1.75,-2.334) 25(1.75,2.334) 26(1.25,2.334) 27(0.749,2.334) 28(0.252,2.334) 29(-0.249,2.334) 30(-0.749,2.334) 31(-1.25,2.334) 32(-1.75,2.334)
  rect 3.2x3.2 smd: 33(0,0)
NPIN787
  round 3.4 hole 2: 1(0,0)
QFN24P_5M_4X4M
  custom 0.07x0.07 smd: 1(-1.975,1.25) 2(-1.975,0.75) 3(-1.975,0.25) 4(-1.975,-0.25) 5(-1.975,-0.75) 6(-1.975,-1.25) 7(-1.25,-1.975) 8(-0.75,-1.975) 9(-0.25,-1.975) 10(0.25,-1.975) 11(0.75,-1.975) 12(1.25,-1.975) 13(1.975,-1.25) 14(1.975,-0.75) 15(1.975,-0.25) 16(1.975,0.25) 17(1.975,0.75) 18(1.975,1.25) 19(1.25,1.975) 20(0.75,1.975) 21(0.25,1.975) 22(-0.25,1.975) 23(-0.75,1.975) 24(-1.25,1.975)
  rect 2.7x2.7 smd: 25(0,0)
R0201
  custom 0.076x0.076 smd: 1(0,0) 2(0,-0.533)
RCPT_USB_5P_DIP_SM
  rect 0.406x1.346 smd: 1(-1.3,2.675) 2(-0.65,2.675) 3(0,2.675) 4(0.65,2.675) 5(1.3,2.675)
  rect 1.905x1.905 smd: MT1(-1.201,0) MT2(1.201,0)
  oval 1.321x2.54 hole 0.711x1.93: MT3(-3.26,0) MT4(3.26,0)
  rect 1.6x1.397 smd: MT5(-3.2,2.45) MT6(3.25,2.45)
SCR_27X17MA
  rect 1.143x0.838 smd: 1(0,1.525) 2(0,-1.525)
SMC0201
  custom 0.076x0.076 smd: 1(-0.267,0) 2(0.267,0)
SMC0402
  custom 0.127x0.127 smd: 1(0,0) 2(0,-0.889)
SMC0603_HI_VALUE
  custom 0.175x0.175 smd: 1(0,0) 2(0,-1.204)
SMC0805
  rect 1.27x1.524 smd: 1(0,0) 2(0,-2.286)
SMF0402
  rect 0.508x0.508 smd: 1(-0.445,0) 2(0.445,0)
SML0805
  rect 1.27x1.524 smd: 1(0,0) 2(0,-2.032)
SMLED0402
  rect 0.508x0.711 smd: 1(0,0) 2(0,-1.111)
SMR0201
  custom 0.076x0.076 smd: 1(0,0) 2(0,-0.533)
SMR0402
  custom 0.127x0.127 smd: 1(0,0) 2(0,-0.889)
SOD123_67X106
  rect 1.194x0.838 smd: 1(0,0) 2(0,-3.048)
SOT23
  rect 1.27x1.016 smd: 1(0,0) 2(0,-2.032) 3(2.286,-1.016)
SOT23_6_SUPER_NOEP_1P22H
  rect 0.99x0.69 smd: 1(-1.295,0.95) 2(-1.295,0) 3(-1.295,-0.95) 4(1.295,-0.95) 5(1.295,0) 6(1.295,0.95)
SSW2RPB
  rect 1.245x1.727 smd: 1(0,2.159) 2(0,-2.159)
SW_SSAJ110100_3P
  round 0.254 hole 0.813 unplated: (-1.5,-1.285) (1.5,-1.285)
  rect 0.6x0.5 smd: 1(-1,0) 2(1,0) C(0,0)
  rect 0.9x0.7 smd: 3(-3,-1.36) 4(3,-1.36)
SYMBOL_NPTH125
  round 3.81 hole 3.18: 1(0,0)
TP30S
  rect 0.762x0.762 smd: 1(0,0)
unnamed#2
  round 1.016 smd: (0,0)

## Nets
4.38V: C6.2(END2) C54.1 L2.2 R111.2 R113.1 R115.1 U45.14(VOS)
5V: C52.2(END2) C55.1 CR1.1(CATHODE) CR2.1(CATHODE) CR9.2(ANODE) FB1.2(FB2) J2A1.5 J4.2(IO_2) J9.1 R2.2 U36.6(VIN) U45.10(AVIN) U45.11(PVIN2) U45.12(PVIN1) U45.13(EN)
GND: C1.2 C3.1(END1) C4.2 C5.2 C6.1(END1) C8.2 C9.1(END1) C10.1(END1) C11.2 C12.1(END1) C13.2 C14.1(END1) C15.1(END1) C16.1(END1) C17.1(END1) C18.1(END1) C19.1(END1) C20.1(END1) C21.1(END1) C22.1(END1) C23.1(END1) C24.1(END1) C25.1(END1) C26.1(END1) C27.1(END1) C28.1(END1) C29.1(END1) C30.1(END1) C31.1(END1) C32.1(END1) C33.1(END1) C34.2 C36.2 C40.2 C41.2 C42.2 C43.2 C44.2 C45.2 C46.2 C47.2 C48.1(END1) C49.1(END1) C50.1(END1) C51.1(END1) C52.1(END1) C53.2 C54.2 C55.2 C56.1(END1) C57.1(END1) EU1.5(GND) EU1.6(\\O\E\) EU1.11(DIE_FLAG) J1.2(GND) J2.2 J2A1.6 J2A1.7 J2B1.7 J3.5(GND) J3.MT1 J3.MT2 J3.MT3 J3.MT4 J3.MT5 J3.MT6 J4.6(IO_6) J5.6(VSS) J5.10(CARD_DET_SW2) J5.G1 J5.G2 J5.G3 J5.G4 J6.4(GND) J6.MH1 J6.MH2 J7.1 J7.5 J7.9 J7.11 J7.13 J7.15 J13.3 J16.5(GND) J16.MT1 J16.MT2 J16.MT3 J16.MT4 J16.MT5 J16.MT6 MGT5.1 MTG1.1 MTG2.1 MTG3.1 MTG4.1 MTG7.1 MTG8.1 Q2.2(S) Q7.1(R2) Q8.2(S) Q9.2(S) Q10.1(R2) Q11.2(S) Q12.1(R2) Q13.1(R2) Q14.1(R2) R4.1 R6.2 R10.1 R11.1 R13.1 R14.1 R15.1 R16.1 R17.1 R18.1 R20.1 R21.1 R22.1 R23.1 R24.1 R25.1 R26.1 R27.1 R28.1 R29.1 R30.1 R31.1 R32.1 R33.1 R35.1 R37.2 R38.2 R73.1 R80.1 R95.1 R98.1 R106.2 R107.2 R108.2 R109.1 R110.1 R112.1 R125.1 SW1.3(MT_1) SW1.4(MT_2) SW1UI1.2(B) SW1UI2.2(B) SW1UI4.2(B) SW1UI5.2(B) TP2.1 TP6.1 TP10.1 TP12.1 TP13.1 TP15.1 U1.5(FB) U1.6(AGND) U1.7(FSW) U1.8(DEF) U1.15(PGND1) U1.16(PGND2) U1.17(THPAD) U2.4(GND3) U2.17(GND1) U2.20(GND2) U2.24(AGND) U2.26(TEST) U2.33(TPAD) U3.2(AGND#2) U3.15(AGND#15) U3.20(BDGND) U4.B1(GND) U5.C1(GND) U5.D1(GND1) U6.B1(GND) U7.C1(GND) U7.D1(GND1) U8.B1(GND) U9.C1(GND) U9.D1(GND1) U10.B1(GND) U11.C1(GND) U11.D1(GND1) U12.B1(GND) U13.C1(GND) U13.D1(GND1) U14.B1(GND) U15.C1(GND) U15.D1(GND1) U16.9(VSS) U16.18(A0) U16.24(A2) U16.25(TPAD) U17.9(VSS) U17.18(A0) U17.23(A1) U17.24(A2) U17.25(TPAD) U18.B1(GND) U19.B1(GND) U20.B1(GND) U21.B1(GND) U22.B1(INH) U22.C1(GND) U22.D1(GND1) U23.B1(GND) U24.B1(GND) U25.B1(INH) U25.C1(GND) U25.D1(GND1) U26.B1(GND) U27.B1(GND) U28.B1(GND) U29.B1(GND) U30.B1(GND) U31.B1(GND) U32.B1(GND) U33.B1(GND) U34.9(VSS) U34.24(A2) U34.25(TPAD) U35.C2(GND1) U35.C3(GND2) U36.5(GND) U36.7(TPAD) U38.6(OVI) U38.13(EP) U39.9(VSS) U39.23(A1) U39.24(A2) U39.25(TPAD) U40.B1(INH) U40.C1(GND) U40.D1(GND1) U41.B1(INH) U41.C1(GND) U41.D1(GND1) U42.B1(INH) U42.C1(GND) U42.D1(GND1) U43.B1(INH) U43.C1(GND) U43.D1(GND1) U44.3(GND) U45.6(AGND) U45.7(FSW) U45.8(DEF) U45.15(PGND1) U45.16(PGND2) U45.17(THPAD)
VBUS: CR1.2(ANODE) J7.20 Q10.2(VOUT2) Q10.3(VOUT1) TP18.1
VBUS_2: C9.2(END2) J3.1(VCC) R8.1 U2.19(VCC)
VBUS_IN: CR8.2(ANODE) J16.1(VCC) Q10.4(VOUT) R96.1
VBUS_OUT: C36.1 J6.1(VCC) U36.1(VOUT)
VIN: C57.2(END2) CR6.2(ANODE) J2A1.8
A0: J1A1.1 R52.2 TP64.1 U15.A1(COM)
A1: J1A1.2 R53.2 TP65.1 U13.A1(COM)
A2: J1A1.3 R54.2 TP66.1 U11.A1(COM)
A3: J1A1.4 R55.2 TP67.1 U9.A1(COM)
A4: J1A1.5 J2B1.9 R56.2 TP68.1 U7.A1(COM)
A5: J1A1.6 J2B1.10 R57.2 TP69.1 U5.A1(COM)
AIN0: R74.2 U15.C2(Y2)
AIN1: R75.2 U13.C2(Y2)
AIN2: R76.2 U11.C2(Y2)
AIN3: R77.2 U9.C2(Y2)
AIN4: R78.2 U7.C2(Y2)
AIN5: R79.2 U5.C2(Y2)
AREF: J2B1.8 J8.3
DIG0: J1B1.1 R64.2 TP70.1 U33.C2(B)
DIG1: J1B1.2 R65.2 TP71.1 U31.C2(B)
DIG2: J1B1.3 R66.2 TP72.1 U29.C2(B)
DIG3: J1B1.4 R67.2 TP73.1 U27.C2(B)
DIG4: J1B1.5 R68.2 TP74.1 U24.C2(B)
DIG5: J1B1.6 R69.2 TP75.1 U21.C2(B)
DIG6: J1B1.7 R70.2 TP76.1 U19.C2(B)
DIG7: J1B1.8 R71.2 TP77.1 U32.C2(B)
DIG8: J2B1.1 R58.2 TP78.1 U30.C2(B)
DIG9: J2B1.2 R59.2 TP79.1 U28.C2(B)
DIG10: J2B1.3 R60.2 TP80.1 U26.C2(B)
DIG11: J2B1.4 J4.4(IO_4) R61.2 TP81.1 U23.C2(B)
DIG12: J2B1.5 J4.1(IO_1) R62.2 TP82.1 U20.C2(B)
DIG13: J2B1.6 J4.3(IO_3) R63.2 TP83.1 U18.C2(B)
DIG13_1P8: Q9.1(G) R87.1 U18.C1(A) U43.A1(COM)
FAULT: J7.19 R36.1 TP19.1 U36.3(F\A\U\L\T\)
FW_RCVR: J7.69 SW1UI3.1(A) TP63.1
GP12_PWM0: J7.35 J12.2 TP34.1
GP13_PWM1: J7.33 J11.2 TP32.1
GP14: J7.48 TP41.1 U6.C1(A)
GP15: J7.42 R122.1 TP88.1 U17.22(\\I\N\T)
GP19: J7.41 Q6.2(S) R44.1 TP37.1 U16.19(SCL) U34.19(SCL)
GP20: J7.43 Q5.2(S) R43.1 TP38.1 U16.20(SDA) U34.20(SDA)
GP27: J7.45 Q3.2(S) R39.1 TP40.1
GP28: J7.47 Q4.2(S) R40.1 TP42.1
GP40: J7.52 TP44.1 U43.B2(Y1)
GP41: J7.54 TP46.1 U40.B2(Y1)
GP42: J7.50 TP43.1 U42.B2(Y1)
GP43: J7.56 TP48.1 U41.B2(Y1)
GP44: J7.24 TP22.1 U14.C1(A)
GP45: J7.26 TP24.1 U12.C1(A)
GP46: J7.28 TP26.1 U10.C1(A)
GP47: J7.30 TP28.1 U8.C1(A)
GP48: J7.32 TP29.1 U32.C1(A)
GP49: J7.34 TP31.1 U30.C1(A)
GP77: J5.9(CARD_DET_SW1) J7.60 R45.2 TP52.1 U35.A3(WP/CD)
GP78: J7.58 TP50.1 U35.D2(CLKA)
GP79: J7.62 TP54.1 U35.C1(CMDA)
GP80: J7.66 TP58.1 U35.D1(DAT0A)
GP81: J7.70 TP62.1 U35.E1(DAT1A)
GP82: J7.64 TP56.1 U35.A1(DAT2A)
GP83: J7.68 TP60.1 U35.B1(DAT3A)
GP84: J7.44 TP87.1 U35.E2(CLK-F)
GP109: J7.55 TP49.1 U3.17(SCLK) U43.C2(Y2)
GP110: J7.53 TP47.1 U3.16(C\S\)
GP111: J7.51 TP45.1 U40.C2(Y2) U44.1(\\O\E\)
GP114: J7.59 TP53.1 U3.19(SDO) U44.4(Y)
GP115: J7.57 TP51.1 U3.18(SDI) U41.C2(Y2)
GP128: J7.65 TP59.1 U29.C1(A)
GP129: J7.63 TP57.1 U24.C1(A)
GP130: J7.61 TP55.1 U33.C1(A)
GP131: J7.46 TP39.1 U31.C1(A)
GP134: J7.22 R7.2 TP20.1
GP135: J7.27 R9.2 TP27.1
GP165: J7.25 TP25.1 U4.C1(A)
GP182_PWM2: J7.37 J12.4 TP35.1
GP183_PWM3: J7.39 J11.4 TP36.1
GPI_PWRBTN_N: J7.17 R49.1 TP17.1
GPI_PWRBTN_N_L: R48.2 R49.2 SW1UI2.1(A)
MSIC_SLPCLK_2: J7.7 TP8.1
OSC_CLK_OUT_0: J7.67 TP61.1
PSW: J7.21 R37.1 TP21.1 U36.4(EN)
PWM0_OUT: J12.1 R91.1 U27.C1(A)
PWM1_OUT: J11.1 R90.1 U21.C1(A)
PWM2_OUT: J12.3 R89.1 U19.C1(A)
PWM3_OUT: J11.3 R92.1 U28.C1(A)
PWM4_OUT: J12.5 R94.1 U25.B2(Y1)
PWM5_OUT: J11.5 R93.1 U22.B2(Y1)
RCVR_MODE: J7.31 SW1UI4.1(A) TP30.1
RESETOUT#: J7.36 Q8.1(G) R85.1 R123.2 TP33.1
SD_CLK: J5.5(CLK) U35.D3(CLKB)
SD_CMD: J5.3(CMD) U35.C4(CMDB)
SD_DAT0: J5.7(DAT0) U35.D4(DAT0B)
SD_DAT1: J5.8(DAT1) U35.E4(DAT1B)
SD_DAT2: J5.1(DAT2) U35.A4(DAT2B)
SD_DAT3: J5.2(CD/DAT3) U35.B4(DAT3B)
SHLD_RESET: C34.1 J2A1.3 J4.5(IO_5) R19.1 SW1UI1.1(A) U17.8(IO0.7) U17.17(IO1.7)
SPI_CLK_SEL: U16.13(IO1.3) U43.D2(A)
SPI_FS_SEL: U16.10(IO1.0) U40.D2(A)
SPI_RXD_SEL: U16.12(IO1.2) U42.D2(A)
SPI_TXD_SEL: U16.11(IO1.1) U41.D2(A)
TRI_STATE_ALL: Q7.5(ON) R35.2 U17.16(IO1.6)
USB_DN: EU1.7(D-) J7.18 TP16.1
USB_DP: EU1.8(D+) J7.16 TP14.1
USB_ID: J7.3 Q11.3(D) TP4.1
USBA_CONN_DN: EU1.2(1D-) J6.2(USB-)
USBA_CONN_DP: EU1.1(1D+) J6.3(USB+)
V_1P80: C10.2(END2) C13.1 C14.2(END2) C15.2(END2) C16.2(END2) C17.2(END2) C18.2(END2) C19.2(END2) C20.2(END2) C22.2(END2) C31.2(END2) J15.2 Q3.1(G) Q4.1(G) Q5.1(G) Q6.1(G) Q13.4(VOUT) R36.2 R39.2 R40.2 R43.2 R44.2 R45.1 R46.1 R47.2 R82.1 R85.2 R87.2 R89.2 R90.2 R91.2 R92.2 R93.2 R94.2 R102.1 TP11.1 U2.1(VCCIO) U3.21(+VBD) U4.A1(VCCA) U6.A1(VCCA) U8.A1(VCCA) U10.A1(VCCA) U12.A1(VCCA) U14.A1(VCCA) U18.A1(VCCA) U19.A1(VCCA) U20.A1(VCCA) U21.A1(VCCA) U22.A2(VCC) U23.A1(VCCA) U24.A1(VCCA) U25.A2(VCC) U26.A1(VCCA) U27.A1(VCCA) U28.A1(VCCA) U29.A1(VCCA) U30.A1(VCCA) U31.A1(VCCA) U32.A1(VCCA) U33.A1(VCCA) U35.A2(VCCA) U40.A2(VCC) U41.A2(VCC) U42.A2(VCC) U43.A2(VCC) U44.6(VCC)
V_1P80_IO: C21.2(END2) C50.2(END2) Q13.2(VOUT2) Q13.3(VOUT1) R107.1 R122.2 U16.21(VDD) U16.23(A1) U34.18(A0) U34.21(VDD) U34.23(A1)
V_3P30: EU1.10(VCC) J2A1.4 J9.3 J14.2 R83.1 TP7.1 TP9.1
V_SHIELD: C23.2(END2) C24.2(END2) C25.2(END2) C28.2(END2) C29.2(END2) C30.2(END2) J2A1.2 J8.1 J9.2 Q7.4(VOUT) Q12.4(VOUT) R12.1 R19.2 R34.1 R41.2 R42.2 R100.1 R114.2 U5.A2(VCC) U7.A2(VCC) U9.A2(VCC) U11.A2(VCC) U13.A2(VCC) U15.A2(VCC)
V_SHIELD_SW: Q7.2(VOUT2) Q7.3(VOUT1) R125.2 U4.A2(VCCB) U6.A2(VCCB) U8.A2(VCCB) U10.A2(VCCB) U12.A2(VCCB) U14.A2(VCCB) U18.A2(VCCB) U19.A2(VCCB) U20.A2(VCCB) U21.A2(VCCB) U23.A2(VCCB) U24.A2(VCCB) U26.A2(VCCB) U27.A2(VCCB) U28.A2(VCCB) U29.A2(VCCB) U30.A2(VCCB) U31.A2(VCCB) U32.A2(VCCB) U33.A2(VCCB)
V_SHLD_IO: C26.2(END2) C27.2(END2) C51.2(END2) Q12.2(VOUT2) Q12.3(VOUT1) R50.2 R51.2 R108.1 R116.2 R117.2 R118.2 R119.2 R120.2 R121.2 U17.21(VDD) U39.18(A0) U39.21(VDD)
V_SYS: C5.1 C32.2(END2) Q14.4(VOUT) R48.1 R86.2 R88.2 R104.1 R105.1 R113.2 TP1.1 TP3.1 TP5.1 U35.B2(VBATT) U38.11(OUT)
V_SYSTEM: C49.2(END2) J10.2 Q14.2(VOUT2) Q14.3(VOUT1) R84.1 R106.1
V_VBAT_BKUP: J7.23 TP23.1
N11374: J3.2(USB-) TP85.1 U2.15(USBDM)
N11378: J3.3(USB+) TP86.1 U2.14(USBDP)
N30036849: R8.2 U2.18(R\E\S\E\T)
N30040341: C33.2(END2) J5.4(VDD) U35.B3(VCCB)
N30044742: R46.2 U35.E3(EN)
N30057553: U3.3(MXO) U3.4(AINP)
N30057571: R10.2 U3.5(AINM)
N30057573: R11.2 U3.23(REFM)
N30057609: C11.1 C12.2(END2) FB1.1(FB1) U3.1(+VA1) U3.14(+VA2)
N30058254: U14.C2(B) U15.B2(Y1)
N30058257: U12.C2(B) U13.B2(Y1)
N30058260: U10.C2(B) U11.B2(Y1)
N30058263: U8.C2(B) U9.B2(Y1)
N30058266: Q4.3(D) R42.1 U6.C2(B) U7.B2(Y1)
N30058269: Q3.3(D) R41.1 U4.C2(B) U5.B2(Y1)
N30061760: R116.1 U15.D2(A) U17.1(IO0.0)
N30061775: R117.1 U13.D2(A) U17.2(IO0.1)
N30061790: R118.1 U11.D2(A) U17.3(IO0.2)
N30061799: R119.1 U9.D2(A) U17.4(IO0.3)
N30061855: R120.1 U7.D2(A) U17.5(IO0.4)
N30061867: R121.1 U5.D2(A) U17.6(IO0.5)
N30061915: R18.2 U4.B2(DIR) U16.6(IO0.5)
N30061925: R17.2 U6.B2(DIR) U16.5(IO0.4)
N30061937: R16.2 U8.B2(DIR) U16.4(IO0.3)
N30061944: R15.2 U10.B2(DIR) U16.3(IO0.2)
N30061956: R14.2 U12.B2(DIR) U16.2(IO0.1)
N30061963: R13.2 U14.B2(DIR) U16.1(IO0.0)
N30062261: Q7.6(R1C1) R12.2 R34.2 U5.B1(INH) U7.B1(INH) U9.B1(INH) U11.B1(INH) U13.B1(INH) U15.B1(INH)
N30066642: R20.2 U33.B2(DIR) U34.1(IO0.0)
N30066644: R21.2 U31.B2(DIR) U34.2(IO0.1)
N30066646: R22.2 U29.B2(DIR) U34.3(IO0.2)
N30066648: R23.2 U27.B2(DIR) U34.4(IO0.3)
N30066650: R24.2 U24.B2(DIR) U34.5(IO0.4)
N30066652: R26.2 U21.B2(DIR) U34.6(IO0.5)
N30067494: R28.2 U19.B2(DIR) U34.7(IO0.6)
N30068975: R33.2 U32.B2(DIR) U34.8(IO0.7)
N30069156: R32.2 U30.B2(DIR) U34.10(IO1.0)
N30069185: R31.2 U28.B2(DIR) U34.11(IO1.1)
N30069197: R30.2 U26.B2(DIR) U34.12(IO1.2)
N30069235: R29.2 U23.B2(DIR) U34.13(IO1.3)
N30069271: R27.2 U20.B2(DIR) U34.14(IO1.4)
N30069280: R25.2 U18.B2(DIR) U34.15(IO1.5)
N30070866: U22.A1(COM) U23.C1(A)
N30070870: U25.A1(COM) U26.C1(A)
N30103916: J8.2 R72.1
N30104433: C46.1 R72.2 R73.2 U3.24(REFP)
N30112835: R38.1 U36.2(ILIM)
N30116209: Q6.3(D) R51.1 U17.19(SCL) U39.19(SCL)
N30116224: Q5.3(D) R50.1 U17.20(SDA) U39.20(SDA)
N30125838: R7.1 U2.30(TXD)
N30125857: R9.1 U2.2(RXD)
N30126826: R47.1 SW1UI3.2(B)
N30126876: J7.2 J7.4 J7.6 J7.14 J10.1 R84.2
N30126894: J7.8 J7.10 J14.1 R83.2
N30126899: J7.12 J15.1 R82.2
N30153200: R110.2 U25.D2(A) U34.17(IO1.7)
N30154037: R52.1 U17.10(IO1.0)
N30154081: R53.1 U17.11(IO1.1)
N30154121: R54.1 U17.12(IO1.2)
N30154162: R55.1 U17.13(IO1.3)
N30154204: R56.1 U17.14(IO1.4)
N30154247: R57.1 U17.15(IO1.5)
N30156263: R58.1 U39.10(IO1.0)
N30156279: R59.1 U39.11(IO1.1)
N30156284: R60.1 U39.12(IO1.2)
N30156311: R61.1 U39.13(IO1.3)
N30156316: R62.1 U39.14(IO1.4)
N30156332: R63.1 U39.15(IO1.5)
N30156954: R64.1 U39.1(IO0.0)
N30156970: R65.1 U39.2(IO0.1)
N30156975: R66.1 U39.3(IO0.2)
N30157002: R67.1 U39.4(IO0.3)
N30157007: R68.1 U39.5(IO0.4)
N30157023: R69.1 U39.6(IO0.5)
N30157147: R70.1 U39.7(IO0.6)
N30157152: R71.1 U39.8(IO0.7)
N30158305: C40.1 R74.1 U3.13(CH0)
N30158329: C41.1 R75.1 U3.12(CH1)
N30158362: C42.1 R76.1 U3.11(CH2)
N30158364: C43.1 R77.1 U3.10(CH3)
N30158410: C44.1 R78.1 U3.9(CH4)
N30158412: C45.1 R79.1 U3.8(CH5)
N30173574: R109.2 U22.D2(A) U34.16(IO1.6)
N30202561: DS1.1(LED1) Q8.3(D)
N30202678: DS1.2(LED2) R86.1
N30202793: DS2.1(LED1) Q9.3(D)
N30202823: DS2.2(LED2) R88.1
N30230113: C48.2(END2) U2.16(3V3OUT)
N30245034: EU1.3(2D+) J16.3(USB+)
N30246500: EU1.4(2D-) J16.2(USB-)
N30246922: EU1.9(S) Q10.5(ON) R95.2 SW1.1
N30246940: Q10.6(R1C1) R96.2
N30255447: R97.1 SW1.C
N30255937: Q11.1(G) R98.2 SW1.2
N30257530: Q12.6(R1C1) R100.2
N30257590: Q13.6(R1C1) R102.2
N30257808: Q14.6(R1C1) R104.2
N30258616: Q14.5(ON) R105.2 R124.1 SW1UI5.1(A)
N30259742: Q12.5(ON) Q13.5(ON) R123.1 R124.2
N30303973: U42.C2(Y2) U44.2(A)
N30303977: U20.C1(A) U42.A1(COM)
N30305120: U22.C2(Y2) U41.A1(COM)
N30305448: U25.C2(Y2) U40.A1(COM)
N30330904: C3.2(END2) C47.1 CR6.1(CATHODE) CR7.1(CATHODE) R3.2 R80.2 U1.10(AVIN) U1.11(PVIN2) U1.12(PVIN1) U1.13(EN)
N30330984: C4.1 U1.9(SS/TR)
N30331038: L1.1 U1.1(SW1) U1.2(SW2) U1.3(SW3)
N30331073: C1.1 CR2.2(ANODE) L1.2 R1.2
N30331087: Q2.1(G) R3.1
N30331321: C8.1 R81.2 R115.2 TP84.1 U38.4(ILIM0) U38.5(ILIM1) U38.12(IN)
N30331325: J13.2 R81.1 U38.3(NTC)
N30331509: R4.2 U38.8(PROG)
N30331521: Q2.3(D) R5.1 R6.1
N30331562: R5.2 U38.1(CLPROG)
N30331635: J2.1 U38.10(BAT)
N30331680: C56.2(END2) CR7.2(ANODE) J1.1(+INPUT)
N30331714: R1.1 R2.1 U1.14(VOS)
N30332962: C53.1 U45.9(SS/TR)
N30333004: R111.1 R112.2 U45.5(FB)
N30333010: L2.1 U45.1(SW1) U45.2(SW2) U45.3(SW3)
N30351958: CR8.1(CATHODE) CR9.1(CATHODE) R97.2
N30369476: DS3.2(LED2) R114.1
N30369490: DS3.1(LED1) U38.2(\\C\H\R\G\)

Pads without a net: J1 3; J2A1 1; J3 4; J7 29 38 40 49; J13 1; J16 4; MTG6 1; U1 4; U2 3 5 6 7 8 9 10 11 12 13 21 22 23 25 27 28 29 31 32; U3 6 7 22 25; U16 7 8 14 15 16 17 22; U17 7; U34 22; U38 7 9; U39 16 17 22; U44 5; U45 4

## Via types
v1: diameter 0.508, hole 0.254, TOP to BOTTOM, 643 vias
v2: diameter 0.254, hole 0.102, TOP to GND, 11 vias
v3: diameter 0.483, hole 0.203, TOP to BOTTOM, 1 via
v4: diameter 0.66, hole 0.356, TOP to BOTTOM, 5 vias

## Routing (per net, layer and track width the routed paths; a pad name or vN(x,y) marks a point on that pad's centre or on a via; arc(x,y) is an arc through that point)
4.38V: length 7.1
  TOP w0.127: v1(48.54,42.45) 48.67,42.32 U45.14
  TOP w0.25: v1(46.38,33.43) 46.61,33.65 R115.1 ; v1(46.38,33.43) 46.89,32.92 R113.1 ; v1(46.38,33.43) 45.7,32.74 C6.2
  TOP w0.3: v1(43.08,41.18) L2.2 v1(45.37,41.18) ; R111.2 v1(47.27,35.71)
  vias: v1(43.46,43.34) v1(44.6,42.45)
5V: length 57.9
  TOP w0.254: J4.2 54.92,32.95 ; J4.2 54.92,31.41 ; J4.2 53.38,32.95 ; J4.2 53.38,31.41
  TOP w0.3: U45.10 50.7,39.91 50.7,39.91 ; v1(111.87,34.09) 111.89,34.1 CR9.2 ; v1(28.96,30.61) 29.21,30.86 29.21,36.58 28.89,36.9 U36.6 ; v1(111.86,34.89) 111.88,34.9 112.23,34.9 112.88,34.26 CR9.2 ; CR9.2 112.88,33.87 112.35,33.33 111.88,33.33 v1(111.87,33.34) ; 98.12,50.63 98.12,50.64 R2.2 ; 49.18,42.45 49.17,42.43 U45.13 ; 50.7,40.92 50.69,40.91 U45.12 ; 48.29,43.46 48.17,43.58 C52.2 ; 50.7,40.41 50.69,40.41 U45.11 ; C52.2 48.17,44.64 48.16,44.65 ; C52.2 48.67,43.97
  TOP w0.381: C55.1 49.13,45.49 ; C55.1 48.16,44.65 ; C55.1 48.16,46.33 ; 105.18,42.53 CR1.1 104.56,43.33 ; 84.03,48.75 J9.1 ; J9.1 85.97,48.75 ; J9.1 85,49.72 ; J9.1 85,47.78 ; J2A1.5 83.19,60.12 ; J2A1.5 81.25,60.12 ; J2A1.5 82.22,59.16 ; J2A1.5 82.22,61.09 ; CR2.1 99.22,47.05 ; CR2.1 97.67,47.05 ; CR2.1 98.44,47.67
  BOTTOM w0.5: v1(28.96,30.61) 30.61,30.61 31.5,29.72 46.36,29.72 49.28,32.64 v1(49.28,33.02)
  vias: v1(48.77,33.66) v1(49.78,33.66) v1(88.8,39.65) v1(88.94,44.84) v1(88.94,44.08) v1(88.94,43.31) v1(88.94,42.55) v1(89.18,40.29) v1(89.18,39.02) v1(89.7,44.84) v1(89.7,44.08) v1(89.7,43.31) v1(89.7,42.55) v1(89.69,39.65) v1(90.2,40.29) v1(90.2,39.02) v1(90.7,39.65) v1(104.32,43.34) v1(104.38,42.25) v1(105.12,42.24)
GND: length 462.6
  TOP w0.2: 16.82,11.03 16.81,11.04 17.5,11.04 17.7,11.24 J7.1 ; v1(105.56,31.02) 105.7,31.15 U40.D1 U40.C1 U40.B1 ; U41.C1 U41.D1 105.58,34.2 v1(105.56,34.19) ; v1(17.83,10.06) 17.98,10.06 18.5,10.58 J7.5 ; U43.B1 U43.C1 U43.D1 91.46,21.49 v1(91.47,21.49) ; v1(89.05,21.49) 89.05,21.49 U42.D1 U42.C1 U42.B1 ; 100.5,27.17 v1(100.5,27.84)
  TOP w0.203: U41.B1 U41.C1
  TOP w0.23: R109.1 v1(106.07,37.11) ; U11.C1 66.59,39.25 66.33,38.99 v1(66.33,38.33) 66.58,38.33 U11.D1 ; U7.D1 71.08,38.33 v1(70.83,38.33) 70.83,38.99 71.09,39.25 U7.C1 ; U10.B1 v1(68.02,43.25) ; v1(110.91,29.89) EU1.5 112.82,29.89 113.3,30.37 ; U25.D1 103.55,34.3 v1(103.76,34.3) ; U4.B1 v1(74.77,43.25) ; U31.B1 v1(58.34,16.03) ; U28.B1 v1(80.18,16.03) ; U21.B1 v1(68.5,16.03) ; U27.B1 v1(63.42,16.03) ; v1(115.47,28.98) 115.47,29.62 115.2,29.89 EU1.6 113.68,29.89 113.3,30.26 113.3,30.37 ; U9.C1 68.84,39.25 68.58,38.99 v1(68.58,38.33) 68.83,38.33 U9.D1 ; U32.B1 v1(73.58,16.03) ; R110.1 v1(105.18,37.11) ; U23.B1 v1(85.26,16.03) ; U19.B1 v1(71.04,16.03) ; U22.D1 103.25,38.7 v1(103.5,38.95) ; U13.D1 64.33,38.33 v1(64.08,38.33) 64.08,38.99 64.34,39.25 U13.C1 ; U29.B1 v1(60.88,16.03) ; U14.B1 v1(63.52,43.25) ; U22.B1 103.54,37.25 v1(103.76,37.47) 103.47,37.75 U22.C1 ; U30.B1 v1(77.64,16.03) ; 113.3,30.37 EU1.11 ; U5.D1 73.33,38.33 v1(73.08,38.33) 73.08,38.99 73.34,39.25 U5.C1 ; U18.B1 v1(90.34,16.03) ; U25.C1 103.47,33.5 v1(103.76,33.22) 103.54,33 U25.B1 ; U6.B1 v1(72.52,43.25) ; U8.B1 v1(70.27,43.25) ; U20.B1 v1(87.8,16.03) ; U26.B1 v1(82.72,16.03) ; U15.C1 62.16,39.25 v1(61.9,38.99) 62.14,38.75 U15.D1 ; U12.B1 v1(65.77,43.25) ; U24.B1 v1(65.96,16.03) ; U33.B1 v1(55.8,16.03)
  TOP w0.25: C21.1 v1(63.02,50.06) ; v1(42.5,35.43) 41.71,35.43 40.97,36.17 40.97,36.53 41,36.55 41,36.58 41.07,36.65 41.1,36.65 41.25,36.81 U38.6
  TOP w0.3: C55.2 v1(44.73,45.49) ; C55.2 v1(45.87,44.48) ; C55.2 v1(45.87,46.64) ; v1(68.63,41.3) C30.1 C17.1 ; v1(81.94,29.36) 82.39,29.36 C27.1 ; v1(31.3,59.37) J5.10 v1(30.13,60.36) ; Q9.2 47.02,25.88 48.9,24 51.18,24 MTG8.1 ; v1(96.5,40.62) 97.23,40.62 C13.2 98.23,40.64 v1(98.33,40.73) ; v1(96.5,40.62) C14.1 ; v1(96.5,40.62) v1(95.5,40.62) ; R15.1 v1(67.5,45.64) ; U2.20 110.26,7.36 v1(110.06,7.16) ; U34.9 67.25,24.75 v1(67.5,25) ; v1(21.08,8.38) 21.34,8.38 21.69,8.74 R37.2 ; v1(16.25,65.4) SW1UI2.2 v1(16.25,62.74) ; 65.84,49 66.23,49 66.23,49 66.48,49 v1(67.01,49.53) ; R10.1 v1(92.25,34.89) ; C11.2 v1(90.33,37.5) ; J6.MH1 116.23,40.73 Q11.2 ; C57.1 v2(100.9,56.55) ; v1(40.18,48.34) Q2.2 v1(41.45,49.45) ; U34.24 66.25,26.32 v1(66.79,25.78) ; U39.23 81.75,25.82 v1(81.79,25.78) ; v1(111.33,7.16) 111.76,7.59 U2.17 111.76,8.38 112.06,8.68 113.11,8.68 C48.1 ; SW1.3 v1(120.62,28.93) ; U45.8 49.16,38.01 v1(49.43,37.75) ; Q10.1 v1(103.22,20.54) ; R80.1 v1(100.26,55.11) ; J5.6 v1(39.43,69.08) ; U45.16 47.66,41.8 v1(47.02,42.45) ; v1(30.05,70.08) J5.G1 v1(31.47,68.79) ; R24.1 v1(62.37,23.5) ; 104.27,60.12 MTG3.1 ; v1(48.67,37.75) 48.66,37.75 U45.7 ; U2.4 109.76,4.32 v1(110.06,4.62) ; R18.1 v1(70.51,45.64) ; C33.1 v1(34.63,53.75) ; R33.1 v1(66.5,20.39) ; v1(48.03,37.75) 48.16,37.88 U45.6 ; R27.1 v1(72.11,24) ; J16.5 v1(118.77,21.79) ; v1(16.28,55.18) SW1UI5.2 v1(16.28,52.53) ; v1(34.8,60.7) J5.G4 v1(34.8,58.04) ; C4.2 v1(106.89,52.55) ; U2.24 108.26,7.62 v1(110.01,5.87) ; R31.1 v1(68.5,20.39) ; C10.1 v1(106.96,2.14) ; Q7.1 v1(86.87,42.8) 87.45,42.8 R125.1 ; U17.24 v1(54,45) ; v1(101.13,35.75) C40.2 100.52,36.07 100.22,36.37 99.74,36.37 99.37,36 U3.15 ; J5.G3 v1(40.77,58.04) ; J5.G3 v1(40.77,60.7) ; J5.G3 v1(39.19,59.38) ; J5.G3 v1(42.22,59.38) ; v1(22.5,65.43) SW1UI1.2 v1(22.5,62.63) ; U36.5 v3(26.75,36.25) ; v1(67.75,50.25) 68,50 U16.9 ; C6.1 45.7,30.94 v1(45.52,30.76) ; v1(64,41.47) 63.95,41.47 63.95,41.55 64,41.5 64.15,41.5 64.36,41.3 C24.1 C19.1 ; R21.1 v1(62.88,26.13) ; U3.2 C12.1 v1(93,36.39) ; v1(72.14,22.99) 72,23.12 R29.1 ; C45.2 v1(94.25,31.62) ; v1(72.16,25.04) 71.99,24.88 R25.1 ; R32.1 v1(67.5,20.39) ; C41.2 v1(100.25,31.62) ; v1(108.79,7.16) 108.75,7.12 U2.26 ; R13.1 v1(65.49,45.64) ; v1(99.06,39.75) 98.42,39.12 97.3,39.12 97,38.82 U3.20 ; v1(61.88,42) C20.1 C23.1 ; v1(116.23,3.32) J3.MT5 v1(117.65,1.86) ; R6.2 42.26,43.71 42.51,43.96 v1(42.51,43.97) ; R14.1 v1(66.5,45.64) ; R73.1 v1(94,40.62) 94.23,40.39 C46.2 95.27,40.39 v1(95.5,40.62) ; C42.2 v1(98.75,31.62) ; v1(95.5,40.62) R11.1 ; v1(62.37,25.25) 62.37,25.25 R22.1 ; v1(70.89,41.3) C29.1 C16.1 ; v1(73.14,41.3) C25.1 C15.1 ; C52.1 v1(47.02,43.97) ; J3.5 v1(116.11,7.82) ; R28.1 65.62,20.44 v1(65.56,20.37) ; v1(47.78,42.45) 48.17,42.06 U45.15 ; R95.1 v1(104.42,21.87) ; C36.2 v1(110.96,45.43) ; SW1.4 v1(120.62,37.31) ; v1(23.86,35.49) R38.2 ; C26.1 v1(52.38,46.5) ; R98.1 v1(117.88,38.13) ; C22.1 v1(64.94,53.55) ; C53.2 v1(48.16,35.71) ; U1.7 106.99,49.85 v4(107.22,50.08) 106.95,50.35 U1.8 ; v1(42.79,68.4) J5.G2 v1(43.95,69.86) ; C9.1 v1(110.49,10.79) ; R26.1 v1(62.88,22.62) ; C8.2 44.71,31.31 v1(44.65,31.24) ; U39.24 v1(81.25,27.91) ; C32.1 v1(37,50.64) ; C31.1 v1(34.63,53) ; R20.1 v1(62.37,27) ; R16.1 v1(68.5,45.64) ; C43.2 v1(97.25,31.62) ; U17.18 55.75,48.71 55.5,48.96 v1(54.86,48.96) ; R23.1 v1(62.88,24.37) ; R4.1 v1(41.75,31.4) ; C18.1 C28.1 v1(66.38,41.3) ; v1(3.75,65.59) SW1UI4.2 v1(3.75,62.68) 3.75,61.53 MGT5.1 ; U17.9 57.25,46 v1(57,46.25) 56.25,45.5 U17.23 ; C56.1 v1(109.4,52.35) ; R30.1 v1(69.51,20.39) ; U16.18 66.5,51.56 v1(67.01,51.05) ; R17.1 v1(69.51,45.64) ; R112.1 v1(46.38,35.71) ; R35.1 v1(80.96,43.75) ; C5.2 v1(43.25,30.79) ; v1(82.5,25) 82.25,24.75 U39.9 ; U1.6 106.93,49.35 v4(107.22,49.06) 107,48.85 U1.5 ; C44.2 v1(95.75,31.62) ; C3.1 v1(103.25,55.67)
  TOP w0.33: C34.2 53.11,39.79 52.88,39.55 52.88,38.54 J4.6
  TOP w0.381: MTG3.1 108.46,60.12 ; MTG3.1 106.35,58.01 ; MTG3.1 106.35,62.23
  TOP w0.5: 120.17,24.24 119.67,23.74 J16.MT6 ; 120.17,24.24 J16.MT4 J16.MT2 120.17,21.64 ; 120.17,24.24 v1(120.17,26.11) ; 120.17,21.64 118.92,21.64 v1(118.77,21.79) ; 120.17,21.64 J16.MT1 J16.MT3 120.17,16.74 ; J16.MT6 v1(117.72,25.31) ; J16.MT6 v1(116.15,23.74) ; v1(117.72,15.73) J16.MT5 119.62,17.29 120.17,16.74 ; J3.MT2 J3.MT4 ; Q8.2 v1(35,35.79) ; v1(117.65,11.29) J3.MT6 v1(116.13,9.77) ; Q9.2 v1(45.82,25.88) ; J3.MT1 J3.MT3 ; 120.17,16.74 v1(120.17,14.68)
  GND w0.254: 53.38,38.03 J4.6 ; J4.6 54.92,36.49 ; J4.6 53.38,36.49 ; J4.6 54.92,38.03 ; J6.4 114.64,51.92 ; J6.4 114.64,50.53 ; J6.4 113.25,51.92 ; J6.4 113.25,50.53
  GND w0.381: J13.3 38.83,44.07 ; J13.3 38.83,42.13 ; J13.3 37.86,43.1 ; J13.3 39.8,43.1 ; J1.2 118.17,65.32 ; J1.2 118.17,61.74 ; J1.2 119.96,63.53 ; J1.2 116.38,63.53 ; 104.24,60.12 MTG3.1 ; MTG3.1 108.46,60.12 ; MTG3.1 106.35,58.01 ; MTG3.1 106.35,62.23 ; MTG7.1 54.28,57.15 ; MTG7.1 52.17,55.04 ; MTG7.1 56.39,55.04 ; MTG7.1 54.28,52.93 ; 120.17,8.93 J3.MT4 ; J3.MT4 120.17,10.66 ; J3.MT4 118.7,9.8 ; 42.5,24.97 J2.2 ; J2.2 43.41,25.88 ; J2.2 42.5,26.8 ; J2.2 41.59,25.88 ; 120.17,22.89 J16.MT4 ; J16.MT4 120.17,24.61 ; J16.MT4 118.7,23.75 ; MTG2.1 34.89,14.16 ; MTG2.1 34.89,10.74 ; MTG2.1 36.6,12.45 ; MTG2.1 33.18,12.45 ; MTG1.1 7.91,33.05 ; MTG1.1 6.2,31.34 ; MTG1.1 4.49,33.05 ; MTG1.1 6.2,34.76 ; MTG8.1 54.28,29.21 ; MTG8.1 52.17,27.1 ; MTG8.1 56.39,27.1 ; MTG8.1 54.28,24.99 ; MGT5.1 6.25,61.14 ; MGT5.1 8.36,59.03 ; MGT5.1 4.14,59.03 ; MGT5.1 6.25,56.92 ; MTG4.1 108.69,11.86 ; MTG4.1 106.58,9.75 ; MTG4.1 104.47,11.86 ; MTG4.1 106.58,13.97 ; 77.14,59.16 J2A1.7 ; J2A1.7 78.11,60.12 ; J2A1.7 77.14,61.09 ; J2A1.7 76.17,60.12 ; 120.17,2.41 J3.MT3 ; J3.MT3 118.7,3.28 ; J3.MT3 120.17,4.14 ; J2B1.7 94.87,11.86 ; J2B1.7 92.94,11.86 ; J2B1.7 93.9,10.9 ; J2B1.7 93.9,12.83 ; J2A1.6 80.65,60.12 ; J2A1.6 79.68,61.09 ; J2A1.6 79.68,59.16 ; J2A1.6 78.71,60.12 ; 120.17,16.37 J16.MT3 ; J16.MT3 118.7,17.23 ; J16.MT3 120.17,18.09
  GND w0.406: 115.51,53.14 J6.MH2 ; J6.MH2 117.8,53.14 ; J6.MH2 117.8,55.44 ; J6.MH2 115.51,55.44 ; 115.51,42.3 J6.MH1 ; J6.MH1 117.8,40 ; J6.MH1 115.51,40 ; J6.MH1 117.8,42.3
  PWR_GND w0.254: J6.4 114.64,51.92 ; J6.4 113.25,50.53 ; J6.4 113.25,51.92 ; J6.4 114.64,50.53
  PWR_GND w0.381: 106.58,9.75 MTG4.1 ; MTG4.1 108.69,11.86 ; MTG4.1 106.58,13.97 ; MTG4.1 104.47,11.86 ; 33.18,12.45 MTG2.1 ; MTG2.1 36.6,12.45 ; MTG2.1 34.89,14.16 ; MTG2.1 34.89,10.74 ; 120.17,18.09 J16.MT3 118.7,17.23 ; MTG3.1 106.35,62.23 ; MTG3.1 104.24,60.12 ; MTG3.1 106.35,58.01 ; MTG3.1 108.46,60.12 ; MGT5.1 6.25,61.14 ; MGT5.1 6.25,56.92 ; MGT5.1 8.36,59.03 ; MGT5.1 4.14,59.03 ; MTG1.1 6.2,34.76 ; MTG1.1 7.91,33.05 ; MTG1.1 6.2,31.34 ; MTG1.1 4.49,33.05 ; 116.38,63.53 J1.2 ; J1.2 119.96,63.53 ; J1.2 118.17,61.74 ; J1.2 118.17,65.32 ; 118.7,23.75 J16.MT4 ; J16.MT4 120.17,22.89 ; J16.MT4 120.17,24.61
  PWR_GND w0.406: J6.MH1 117.8,42.3 ; J6.MH1 115.51,42.3 ; J6.MH1 115.51,40 ; J6.MH1 117.8,40 ; 115.51,53.14 J6.MH2 ; J6.MH2 117.8,53.14 ; J6.MH2 115.51,55.44 ; J6.MH2 117.8,55.44
  BOTTOM w0.3: v1(54.86,48.96) 54.28,49.54 MTG7.1 ; v1(17.5,8) TP6.1 v1(16.55,7) ; v1(19,3) TP2.1 ; v1(36.48,6.76) 36.23,7 TP13.1 ; TP15.1 v1(31,3) ; TP12.1 v1(25,5.5) ; TP10.1 v1(26.5,8)
  BOTTOM w0.381: MTG3.1 108.46,60.12 ; MTG3.1 106.35,58.01 ; MTG3.1 106.35,62.23 ; MTG3.1 104.24,60.12
  vias: v1(15.88,11.31) v1(16.69,7.75) v1(16.82,10.1) v1(18.49,7.98) v1(21.74,57.94) v1(21.74,54.13) v1(21.74,50.06) v1(22.51,57.94) v1(22.51,54.13) v1(22.51,50.06) v1(41.15,35.94) v1(41.15,34.93) v1(43.81,35.94) v1(43.81,34.93) v1(56.26,47.05) v1(56.26,45.53) v1(57.79,47.05) v1(57.79,45.53) v1(66.79,24.26) v1(68.19,25.78) v1(68.31,24.26) v1(68.53,51.05) v1(68.53,49.53) v1(81.79,24.26) v1(83.19,25.78) v1(83.31,24.26) v1(103.76,63.75) v1(104.65,63.75) v1(105.54,63.75) v1(106.43,63.75) v1(107.44,63.75) v1(108.33,63.75) v1(108.79,5.89) v1(108.79,4.62) v1(111.2,4.62) v1(111.33,5.89) v2(37.5,53.95) v2(37.5,53.55) v4(48.41,40.16) v4(102.39,49.06) v4(104.77,49.6)
